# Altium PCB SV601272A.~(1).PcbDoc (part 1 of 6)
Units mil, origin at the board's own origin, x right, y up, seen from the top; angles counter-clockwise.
Board outline 8300 x 9520 mil, 8 copper layers (Top Layer, Signal Layer 1, Signal Layer 2, Signal Layer 3, Signal Layer 4, Signal Layer 5, Signal Layer 6, Bottom Layer), stack 59.2 mil thick; 551 components, 303 nets, 1611 pads, 1923 vias.
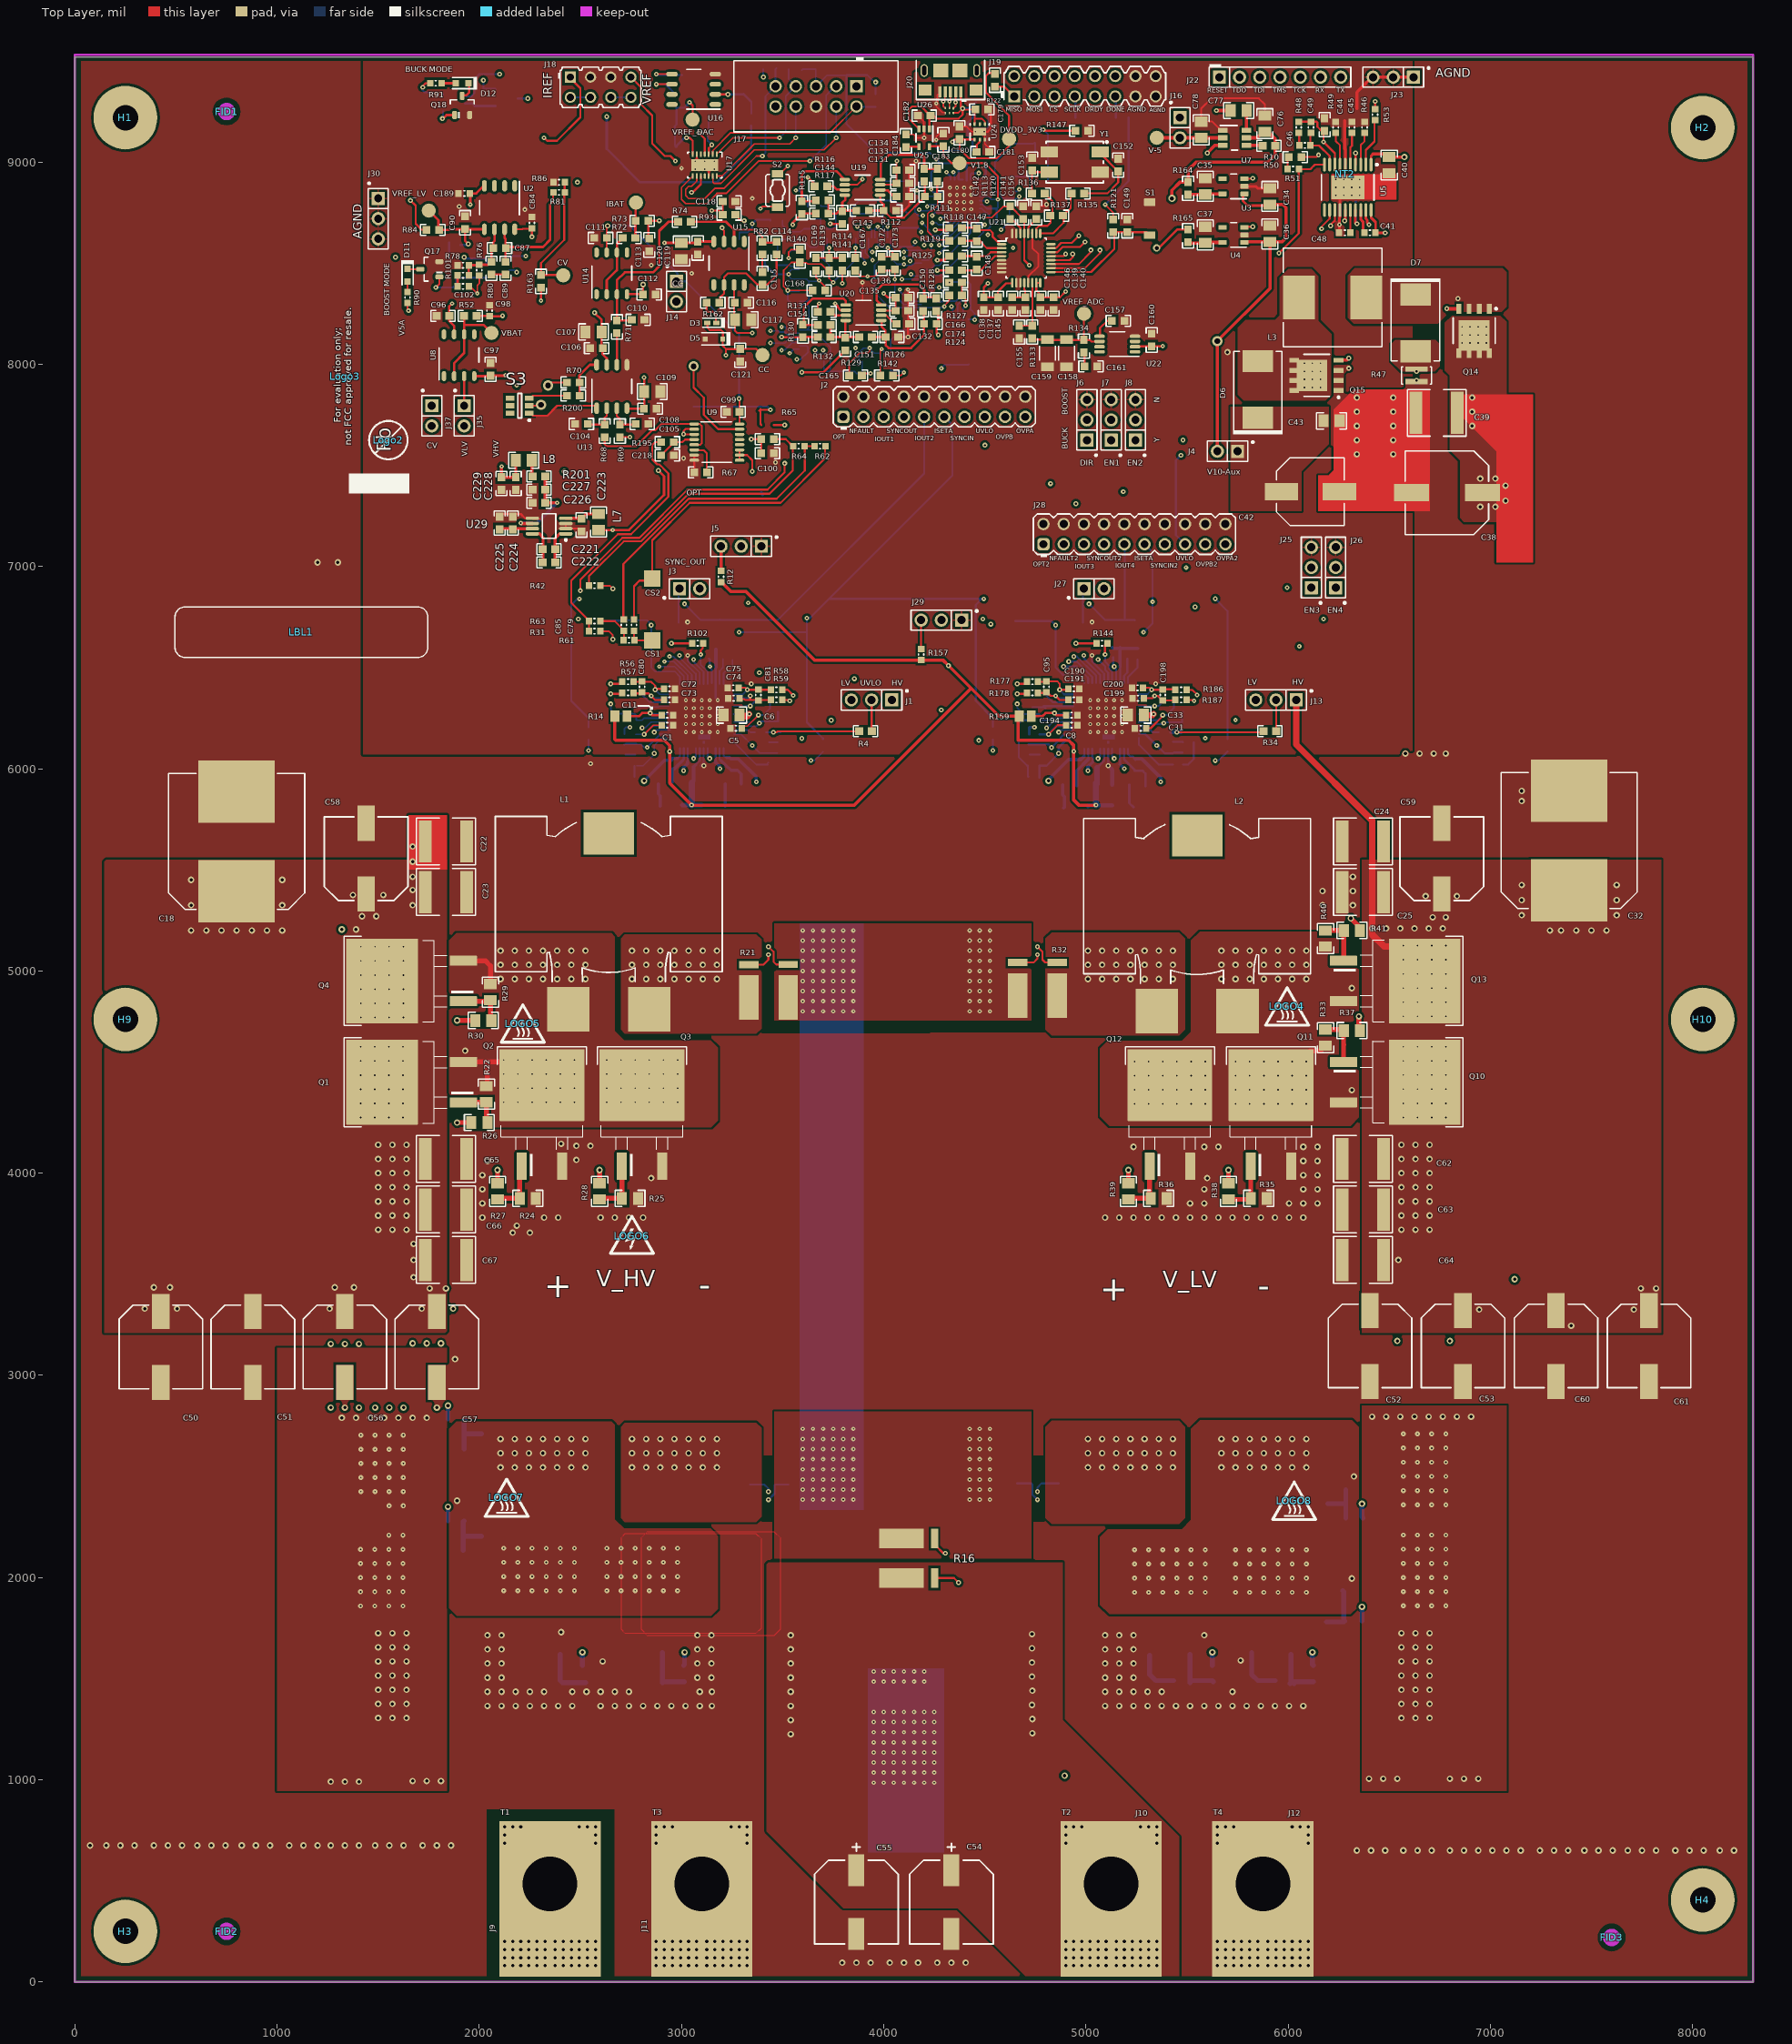
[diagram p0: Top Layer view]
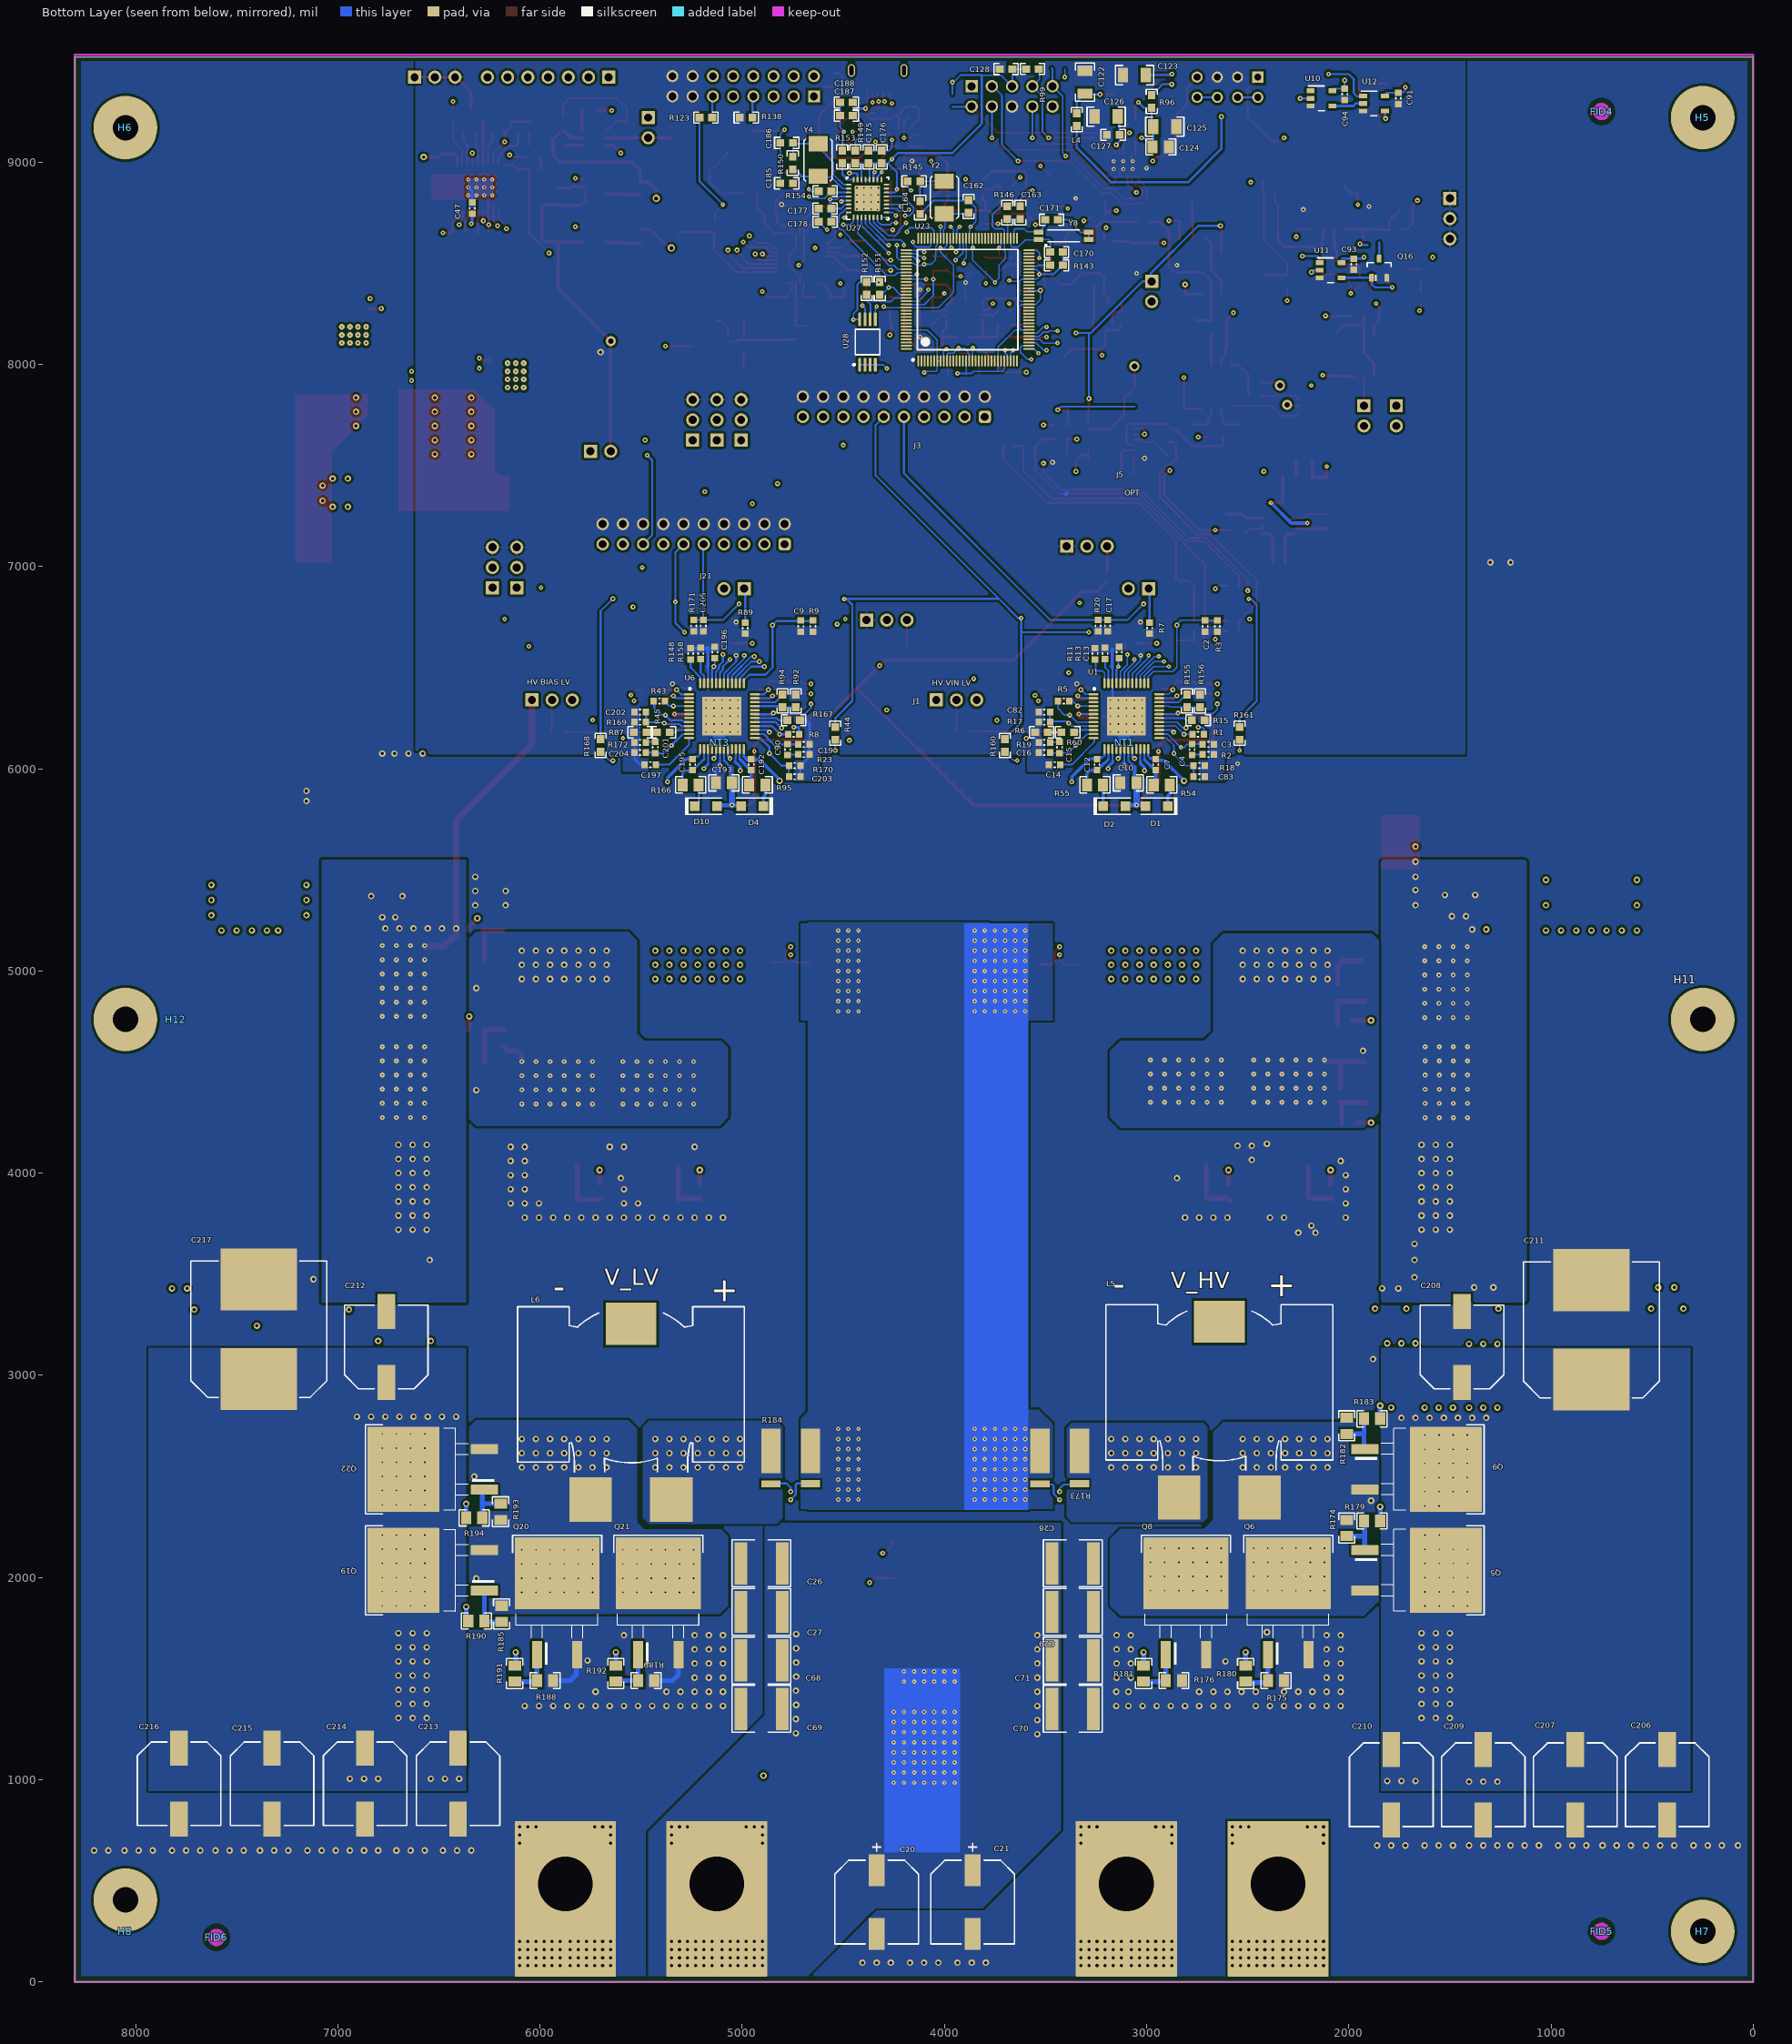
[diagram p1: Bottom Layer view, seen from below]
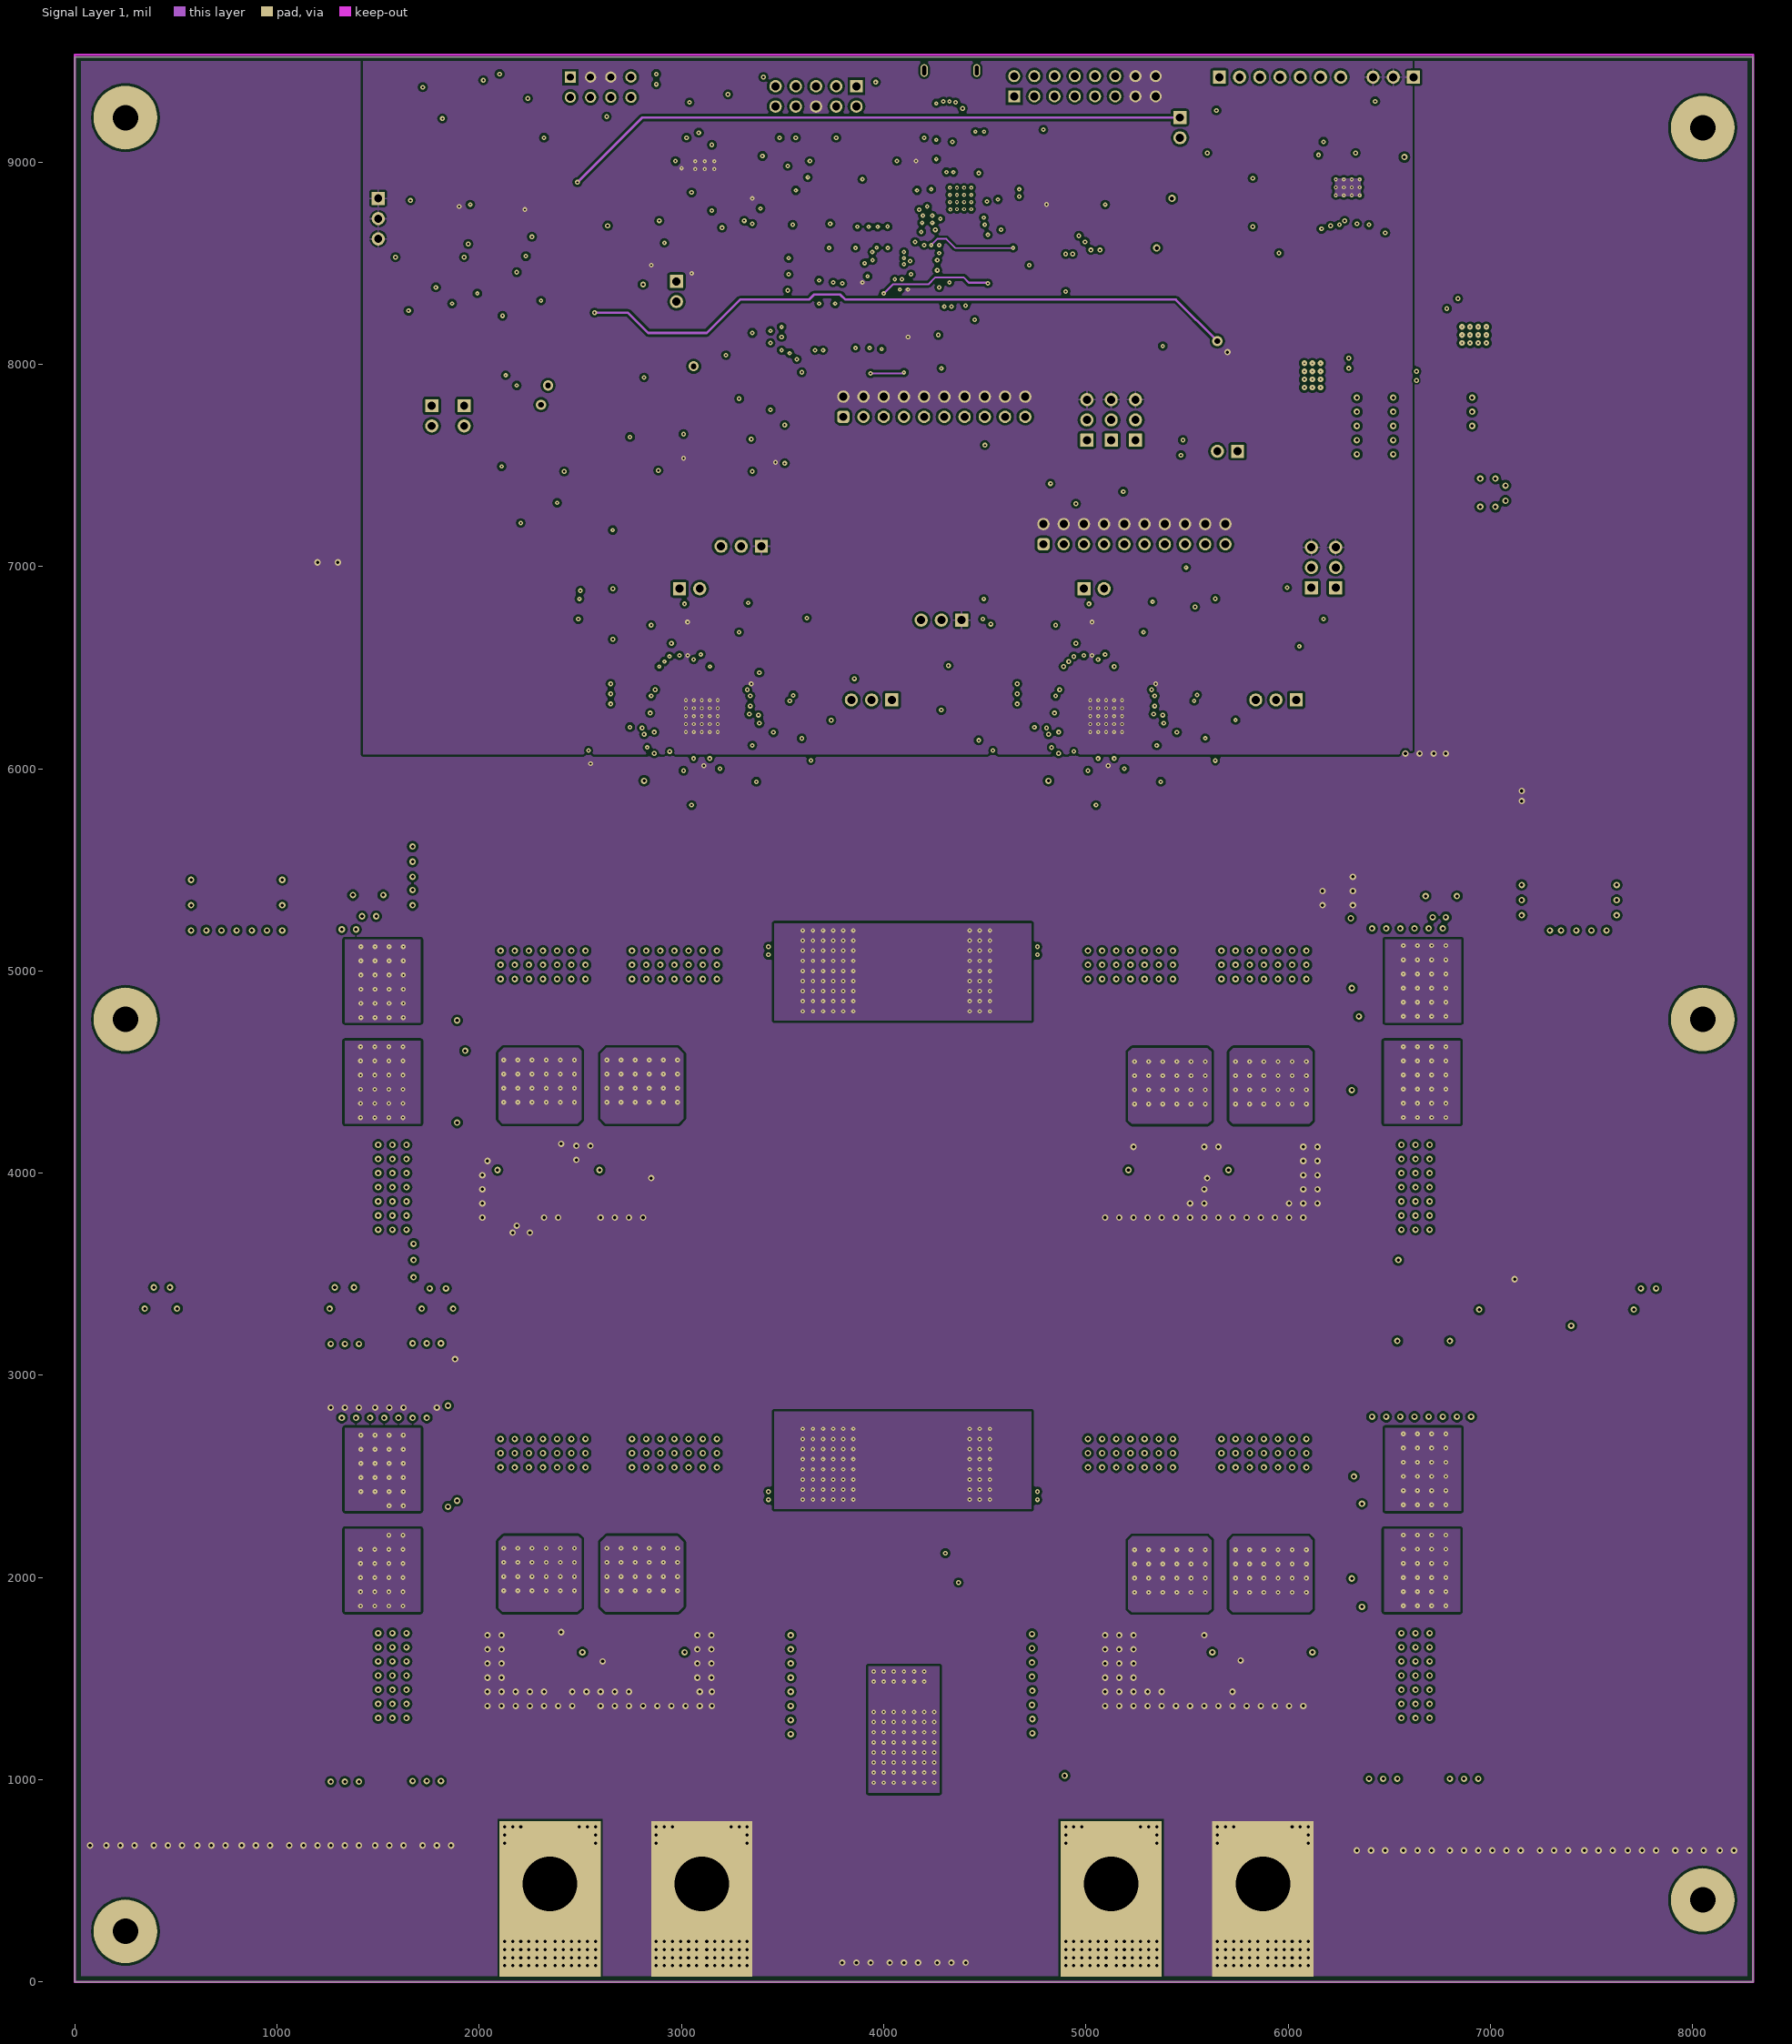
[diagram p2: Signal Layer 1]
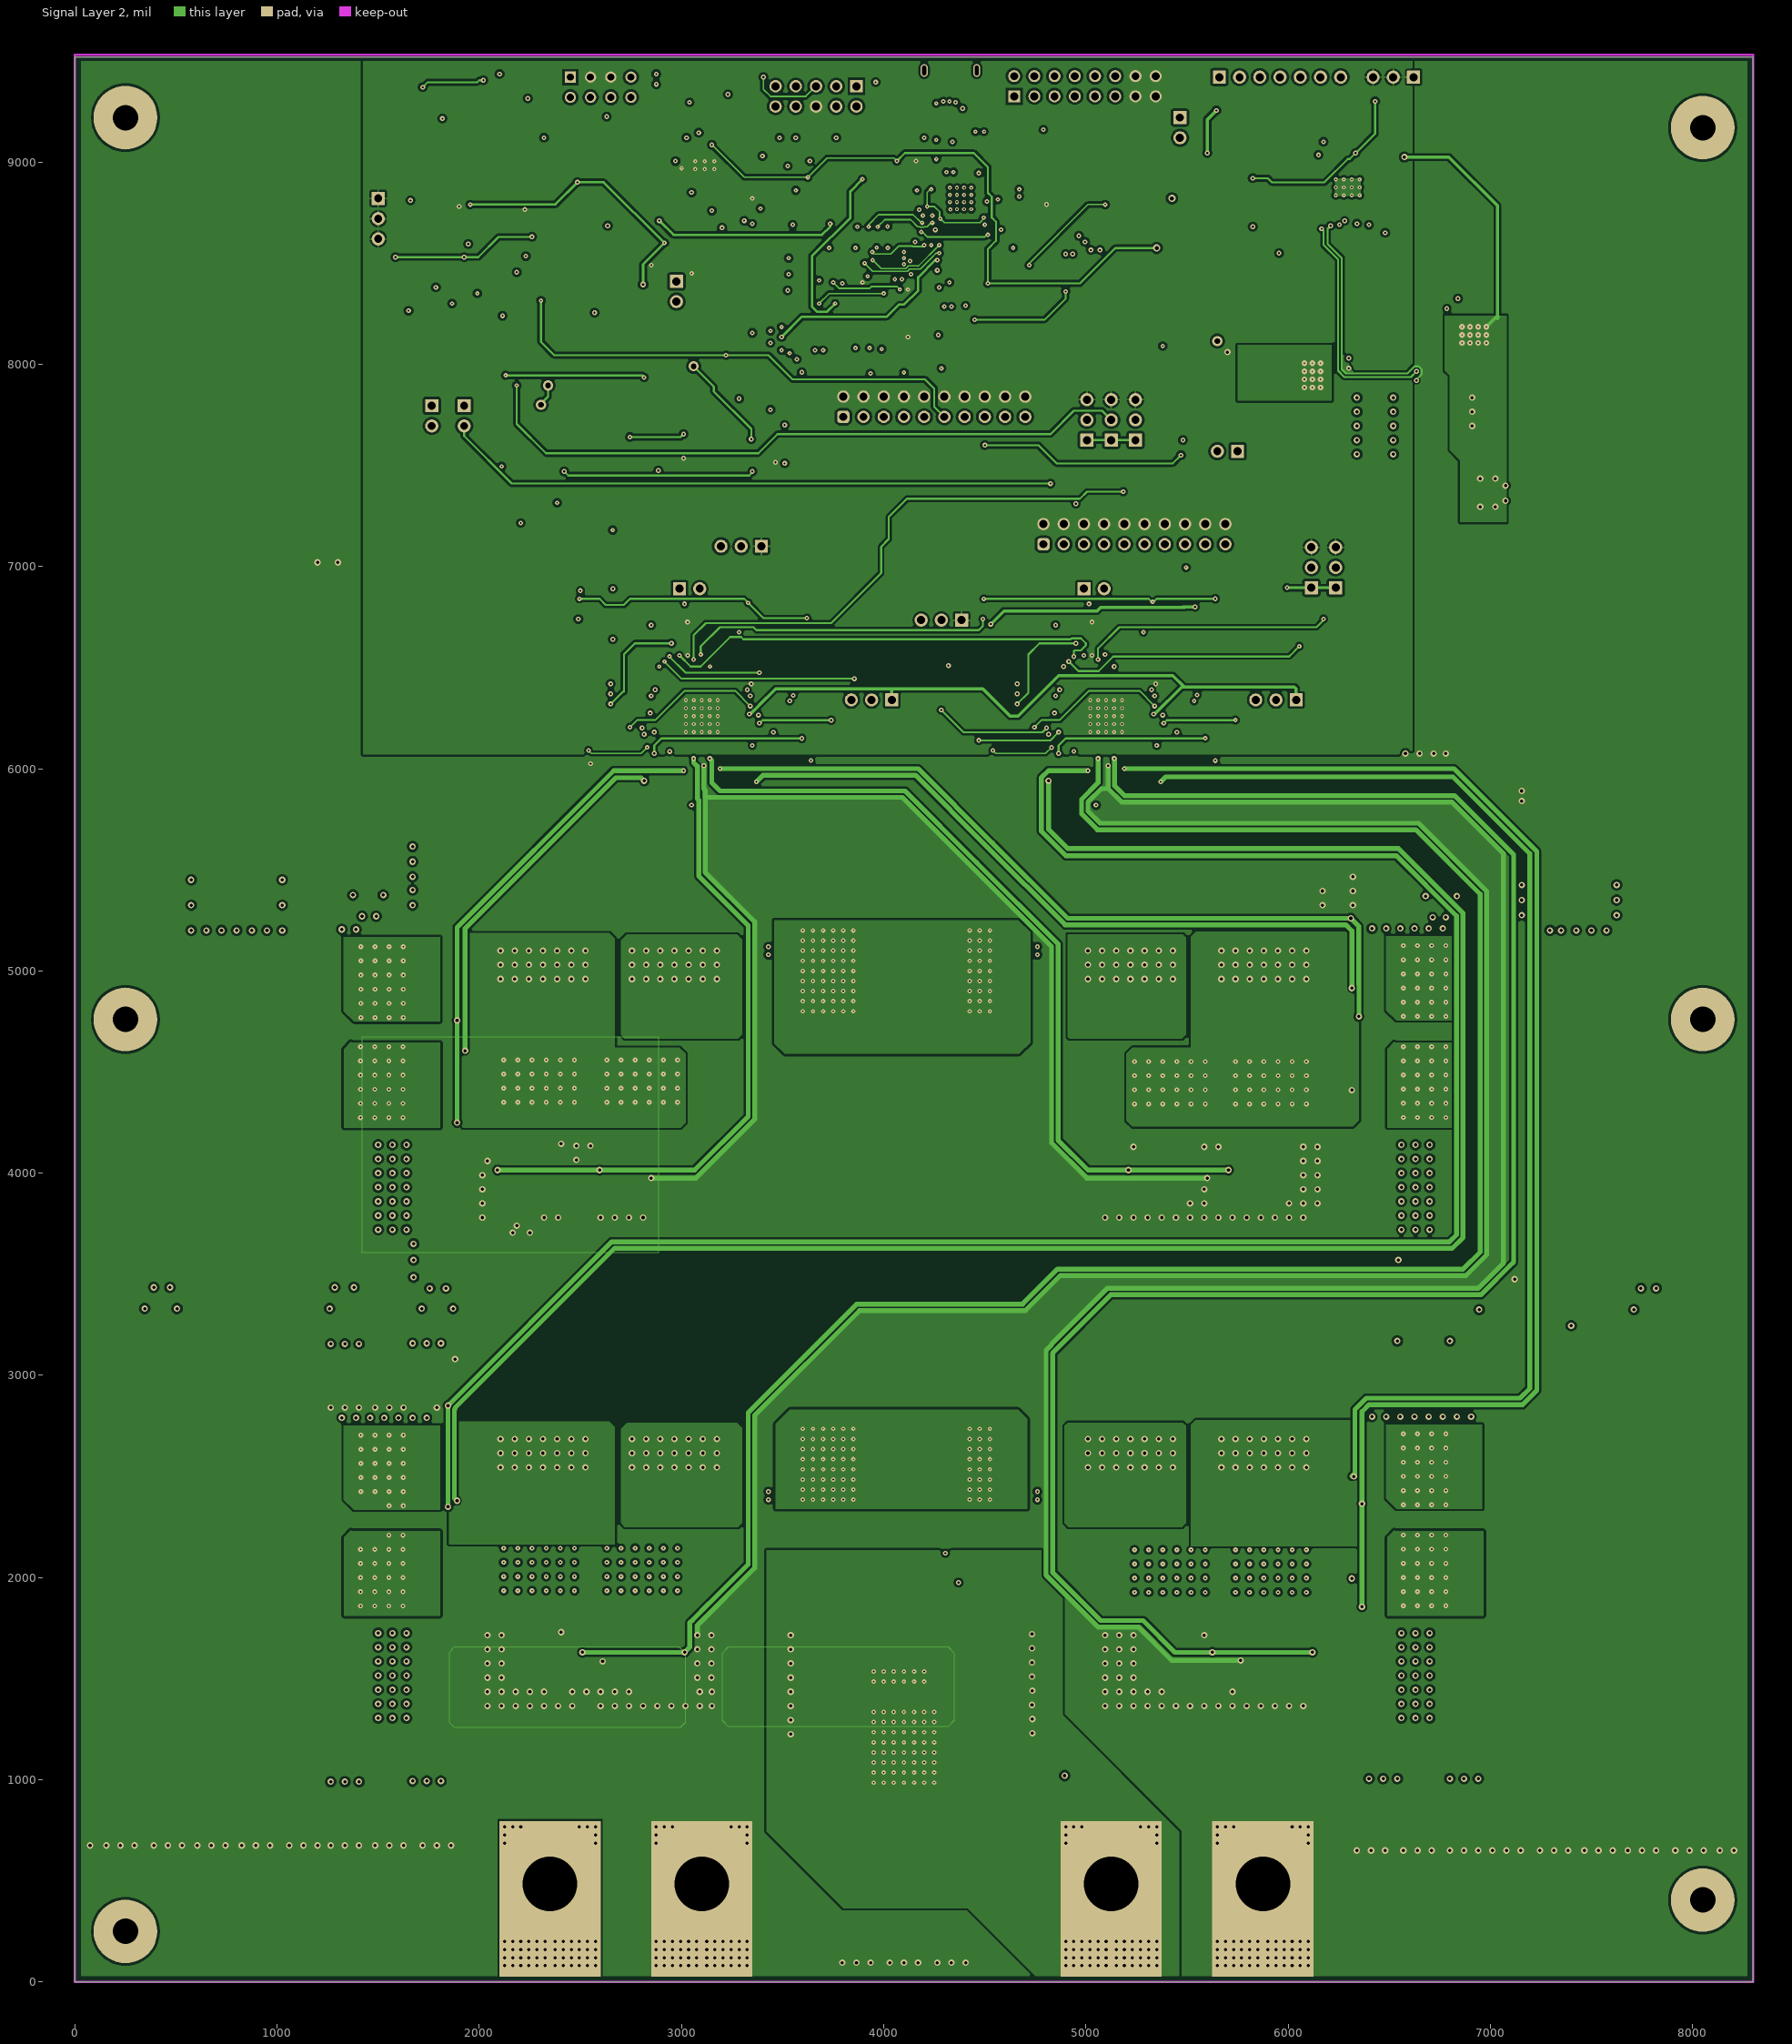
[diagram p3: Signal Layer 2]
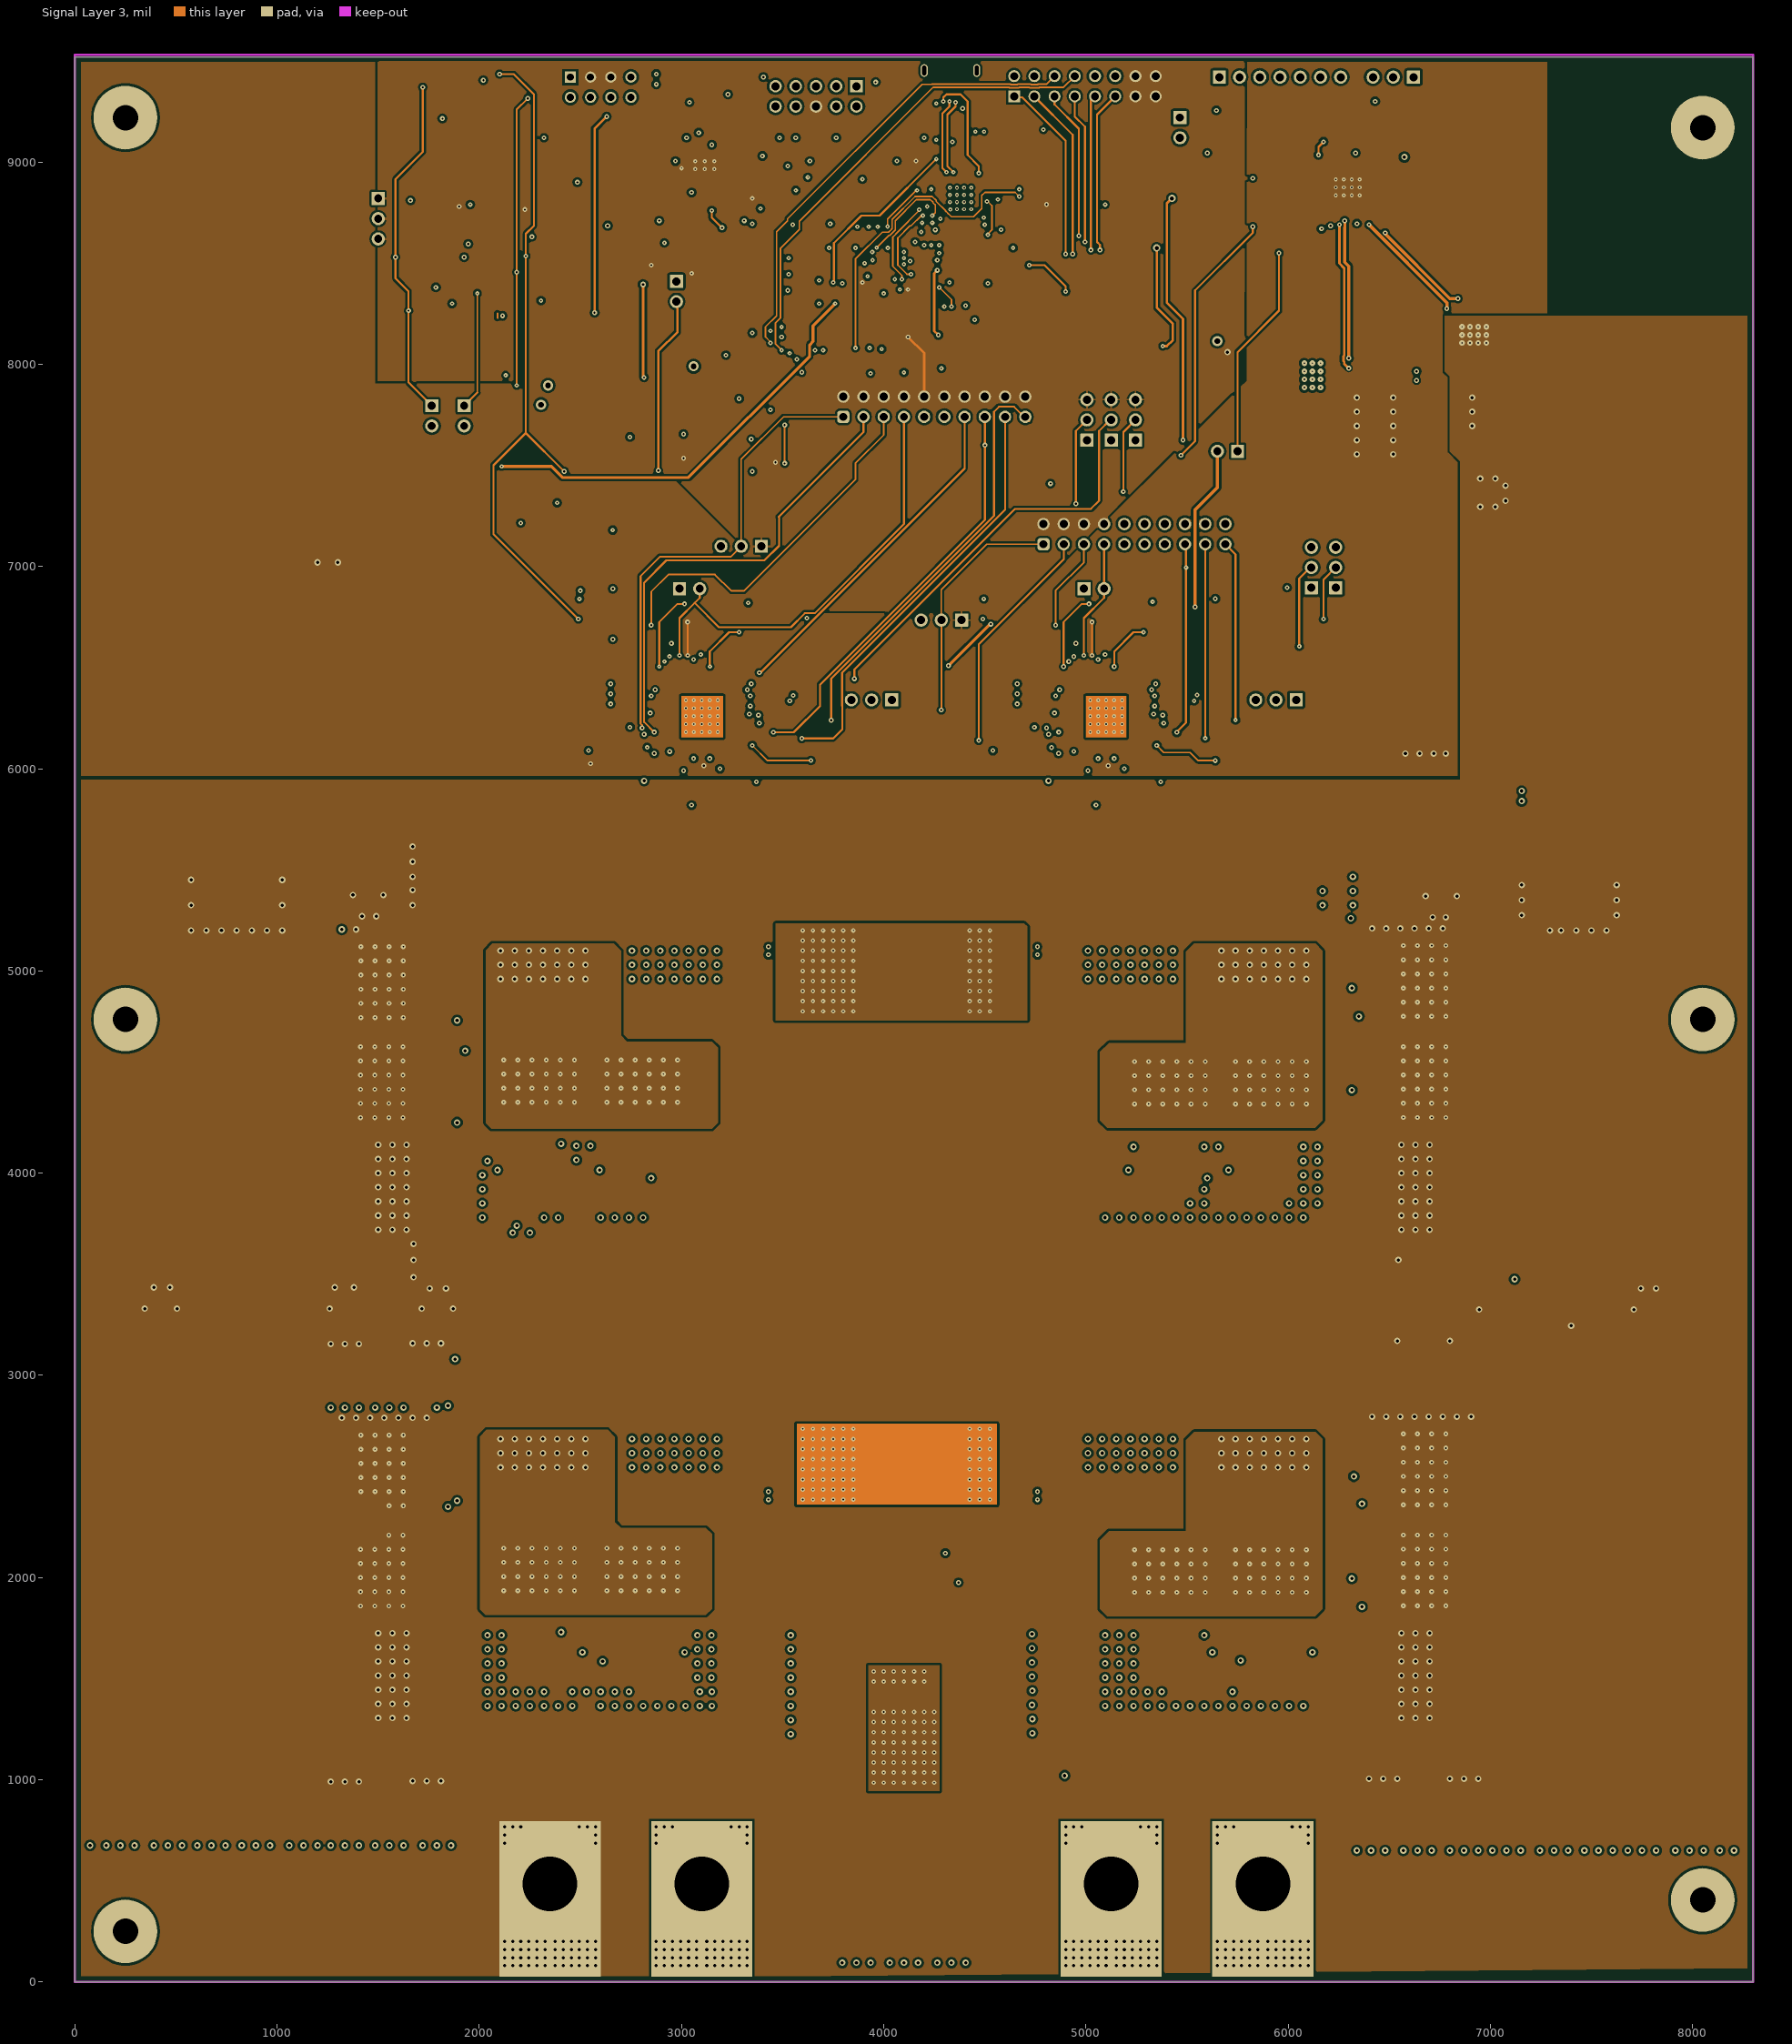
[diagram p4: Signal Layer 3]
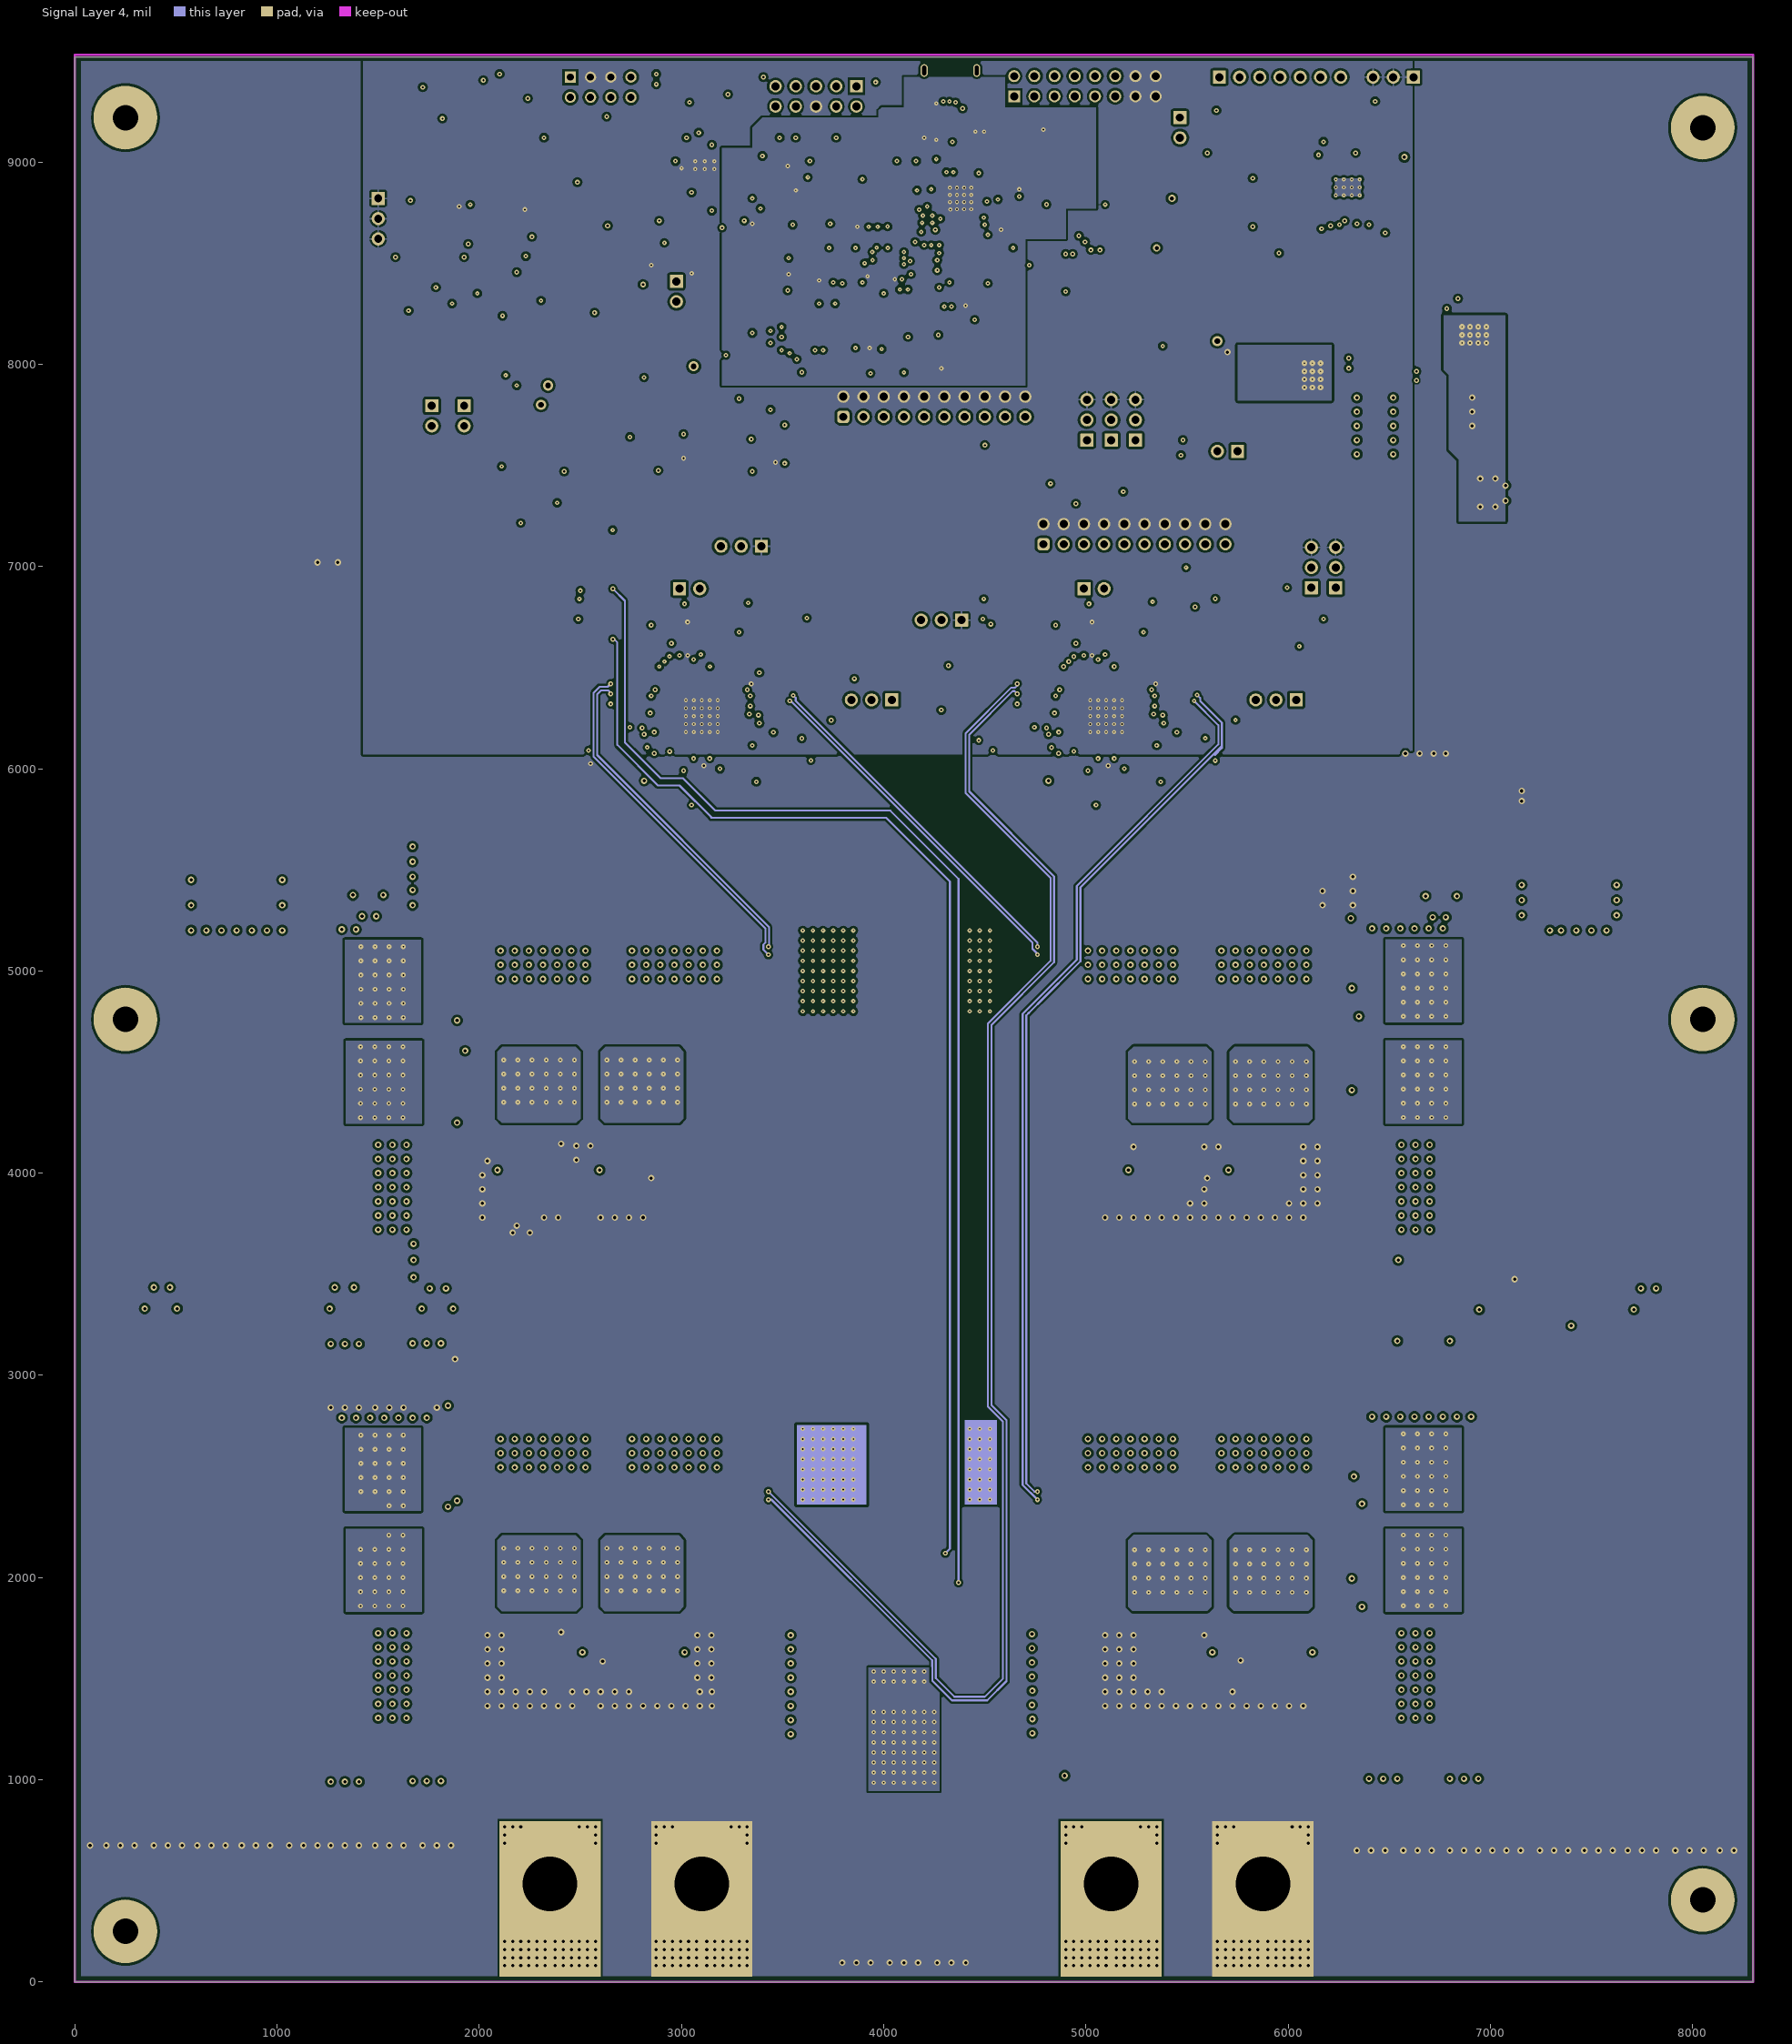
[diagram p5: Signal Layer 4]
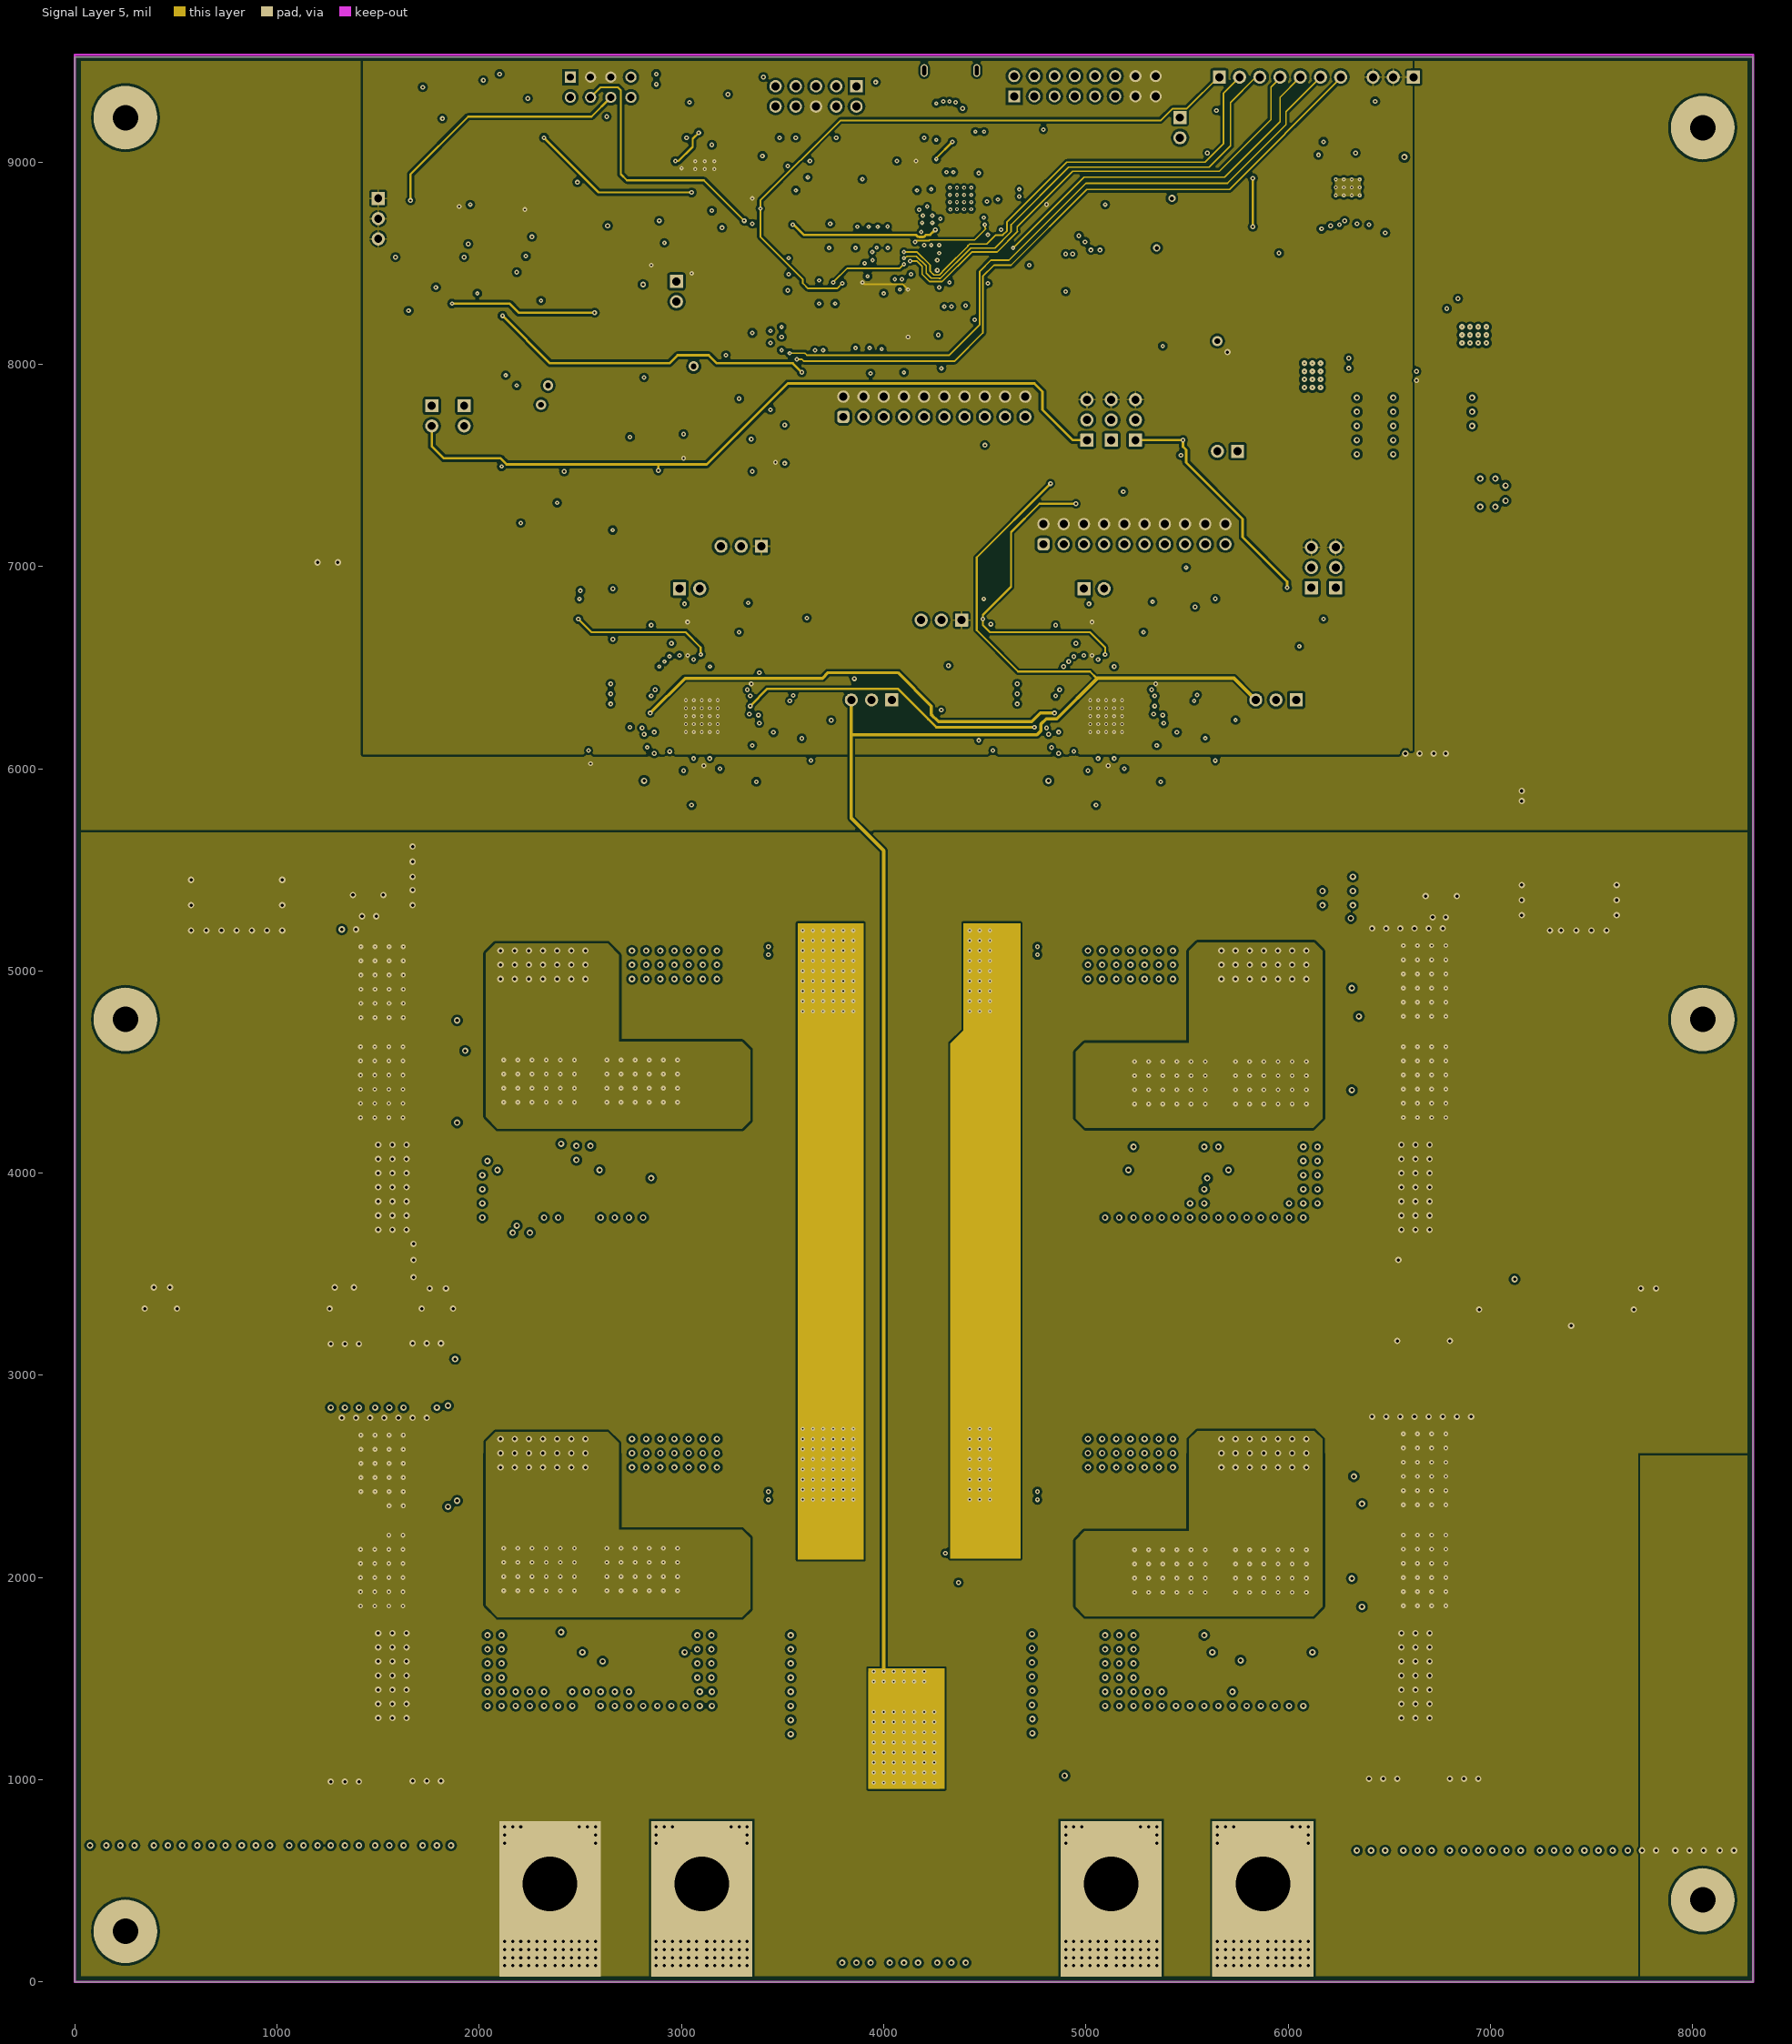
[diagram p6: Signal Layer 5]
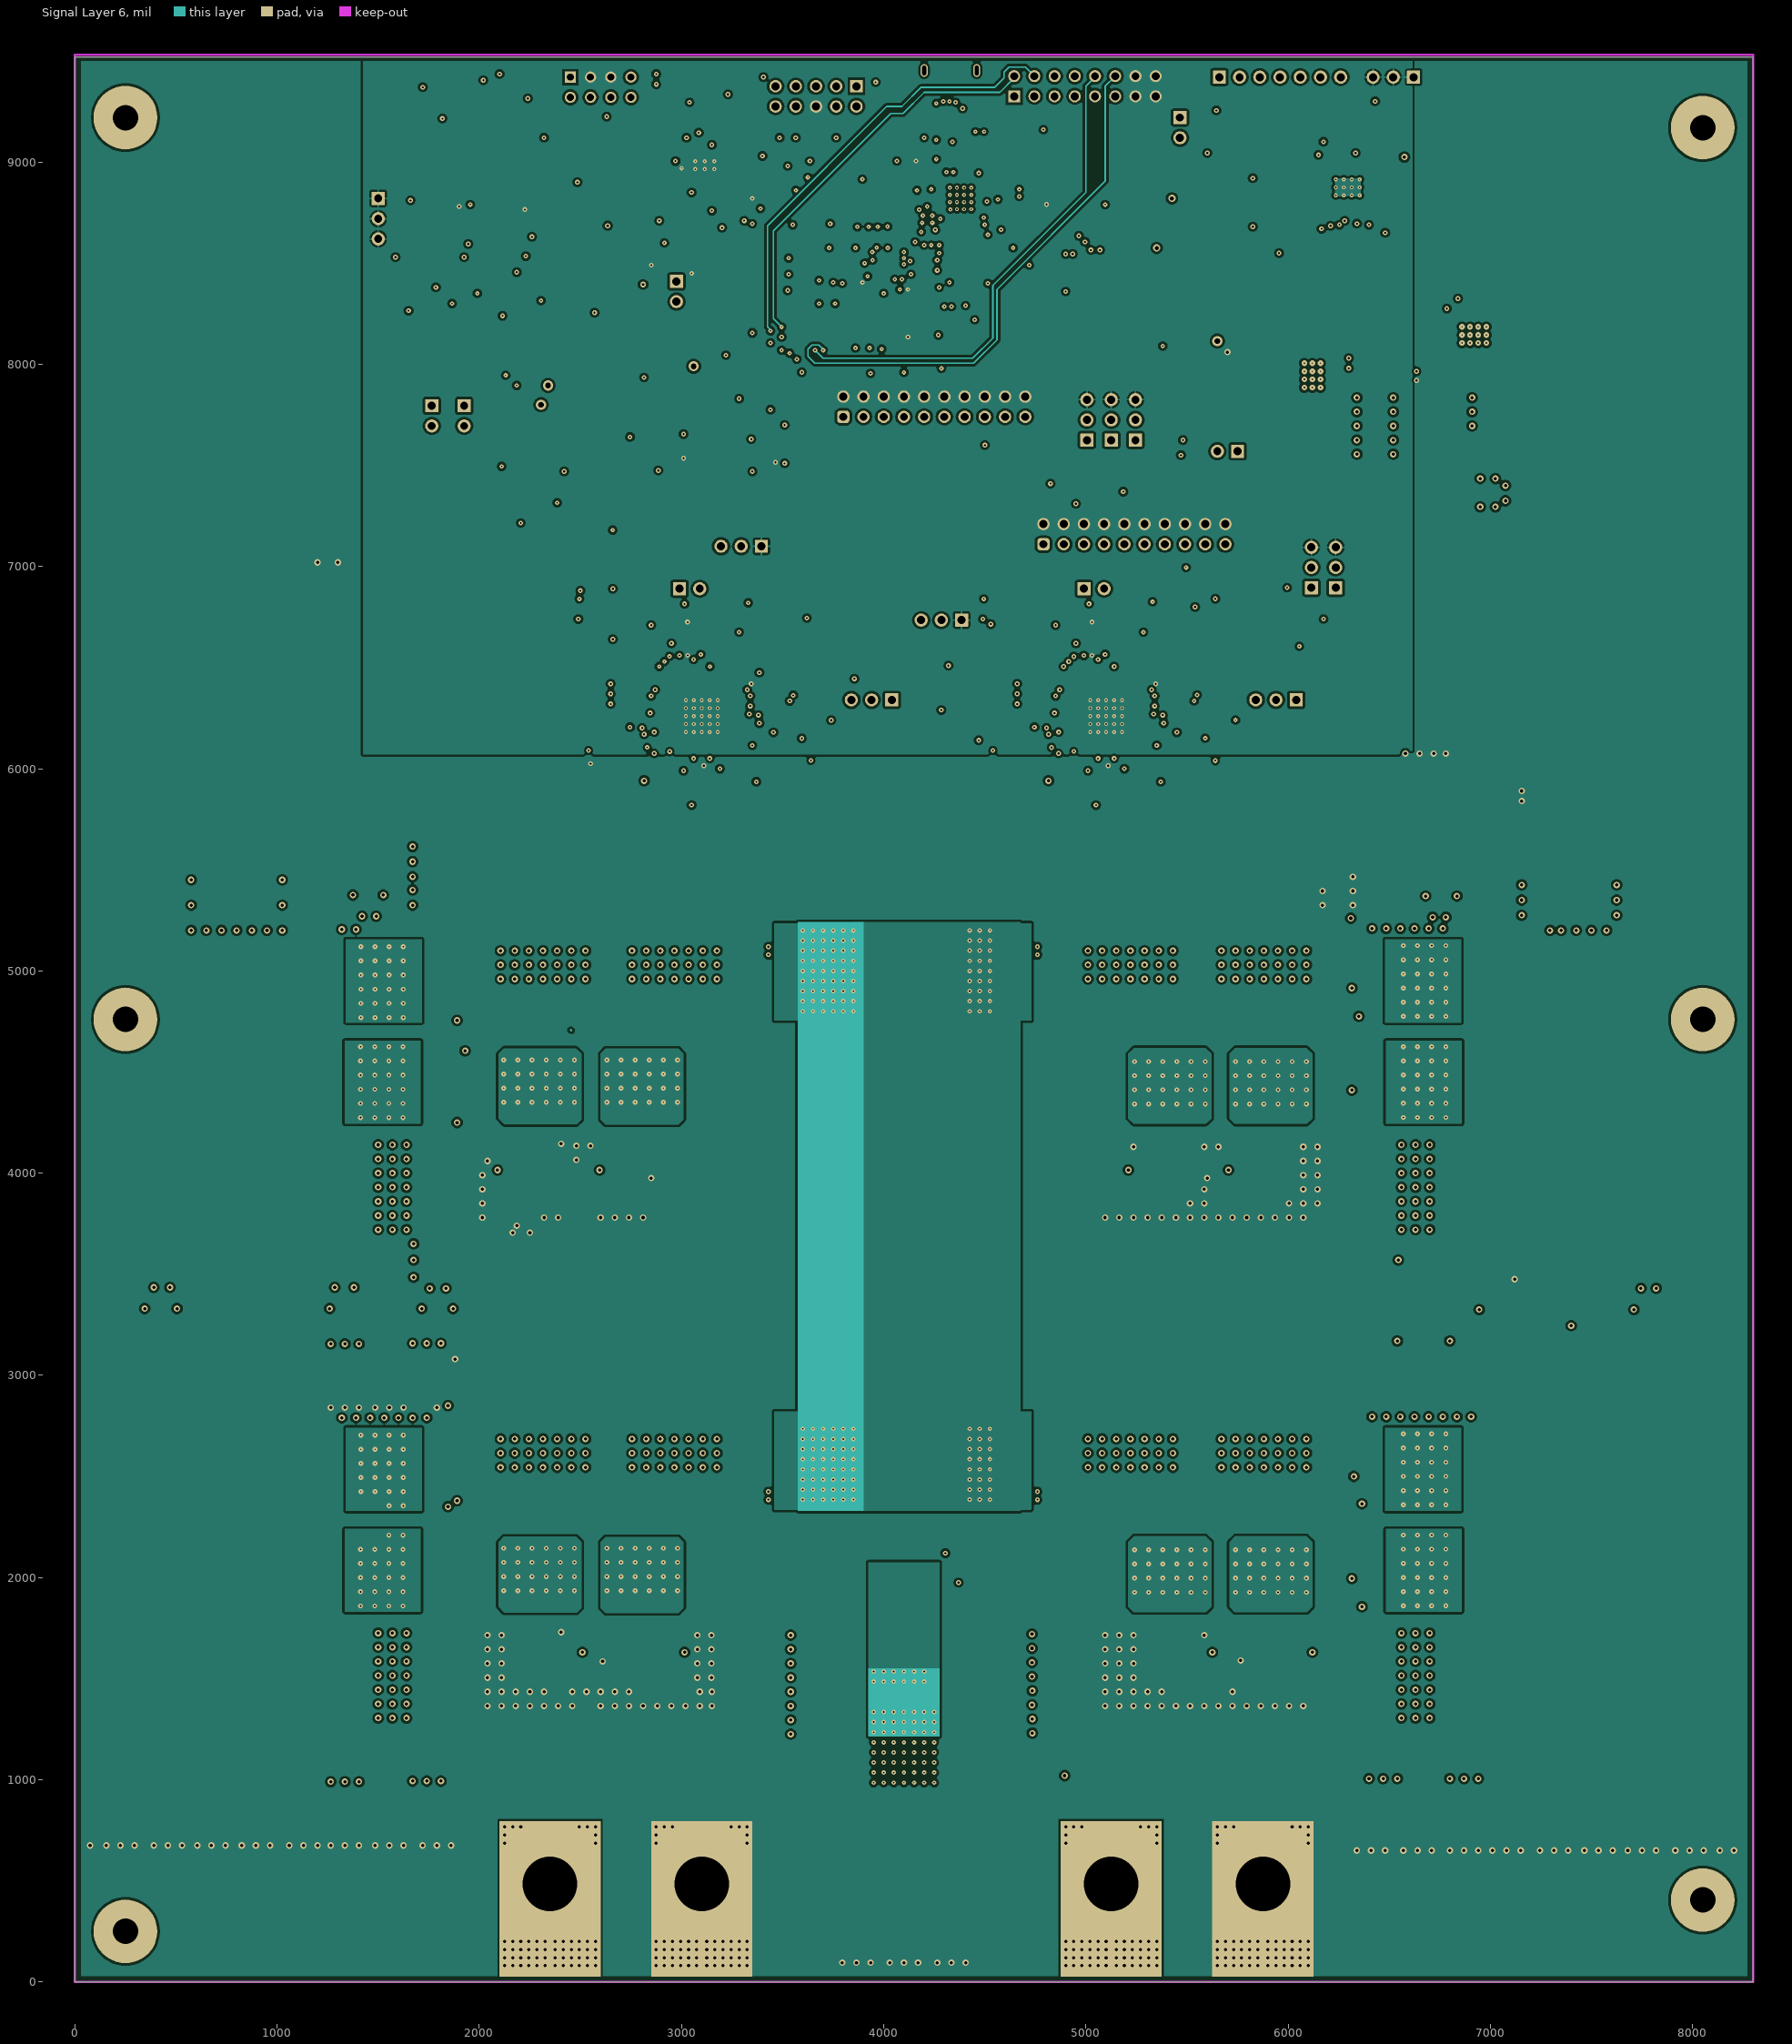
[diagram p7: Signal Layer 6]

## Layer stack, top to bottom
Top Solder: solder mask 0.4, Solder Resist, Dk 3.5
Top Layer: signal copper 3.2
Dielectric1: core 5, FR-4, Dk 4.8
Signal Layer 1: signal copper 2.8
Dielectric 2: prepreg 5, FR-4, Dk 4.2
Signal Layer 2: signal copper 2.8
Dielectric 3: core 5, FR-4, Dk 4.2
Signal Layer 3: signal copper 2.8
Dielectric4: prepreg 6, FR-4, Dk 4.2
Signal Layer 4: signal copper 2.8
Dielectric 5: core 5, FR-4, Dk 4.2
Signal Layer 5: signal copper 2.8
Dielectric 6: prepreg 5, FR-4, Dk 4.2
Signal Layer 6: signal copper 2.8
Dielectric 7: core 5, FR-4, Dk 4.2
Bottom Layer: signal copper 3.2
Bottom Solder: solder mask 0.4, Solder Resist, Dk 3.5

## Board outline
0,0 0,9520 8300,9520 8300,0

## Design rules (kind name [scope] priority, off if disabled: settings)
AcuteAngle [All] p1: minimum=3.30000000000000E+0001 checktracksonly=FALSE
AssemblyTestPointUsage [All] p1: valid=2
Clearance Clearance_USB [InComponent('J20') vs OnLayer('Keep-Out Layer')] p1: gap=30 ignorepadtopadclearanceinfootprint=FALSE
Clearance Clearance_Lugs2BoardEdge [HasFootprint('Panduit_CXS70-14-C') vs IsKeepOut] p2: gap=0 ignorepadtopadclearanceinfootprint=FALSE
Clearance Clearance_Keepouts [((IsTrack Or IsArc) And Not InPoly) And IsFree and IsKeepOut vs ((IsTrack Or IsArc) And Not InPoly) And IsFree and IsKeepOut] p3: gap=0 ignorepadtopadclearanceinfootprint=FALSE
Clearance Clearance_BoardEdge_MountingHoles [OnCopper and InComponentClass('Mounting Holes') vs IsKeepOut] p4: gap=40 ignorepadtopadclearanceinfootprint=FALSE except(0: Arc-Hole Track-Hole SMDPad-Hole THPad-Hole Via-Hole Fill-Hole Poly-Hole Region-Hole Text-Hole)
Clearance Clearance_BoardEdge_Poly [OnCopper and InPoly vs IsKeepOut] p5: gap=25 ignorepadtopadclearanceinfootprint=FALSE except(0: Arc-Hole Track-Hole SMDPad-Hole THPad-Hole Via-Hole Fill-Hole Poly-Hole Region-Hole Text-Hole)
Clearance Clearance_BoardEdge [OnCopper and Not InComponentClass('Logo') and not InComponentClass('FiducialMark') and not InRegion(1000,500,4000,800) and Not IsKeepout vs IsKeepOut] p6: gap=40 ignorepadtopadclearanceinfootprint=FALSE
Clearance Clearance_Poly [InPolygon] p7: gap=11.9 ignorepadtopadclearanceinfootprint=FALSE except(0: Arc-Hole Track-Hole SMDPad-Hole THPad-Hole Via-Hole Fill-Hole Poly-Hole Region-Hole Text-Hole)
Clearance [All] p8: gap=7.87 ignorepadtopadclearanceinfootprint=FALSE except(0: Arc-Hole Track-Hole SMDPad-Hole THPad-Hole Via-Hole Fill-Hole Poly-Hole Region-Hole Text-Hole)
ComponentClearance ComponentClearance_NetTie1 [HasFootprint('PHP0048D_L') vs HasFootprint('Net-Tie_10mil')] p1: gap=0 collisioncheckmode=3 verticalgap=0 showdistances=FALSE
ComponentClearance ComponentClearance_NetTie2 [HasFootprint('MXA20A_N') vs HasFootprint('Net-Tie_10mil')] p2: gap=0 collisioncheckmode=3 verticalgap=0 showdistances=FALSE
ComponentClearance ComponentClearance_Lugs2Banana [HasFootprint('Panduit_CXS70-14-C') vs HasFootprint('Johnson_108-0740-001')] p3: gap=0 collisioncheckmode=3 verticalgap=0 showdistances=FALSE
ComponentClearance ComponentClearance_MountingHoles_FiducialMarks [InComponentClass('Mounting Holes') vs InComponentClass('FiducialMark')] p4: gap=50 collisioncheckmode=3 verticalgap=10 showdistances=FALSE
ComponentClearance ComponentClearance_Shunt [InComponentClass('Header') vs InComponentClass('Shunt')] p5: gap=0 collisioncheckmode=3 verticalgap=0 showdistances=FALSE
ComponentClearance ComponentClearance_Logo [InComponentClass('Logo')] p6: gap=50 collisioncheckmode=3 verticalgap=10 showdistances=FALSE
ComponentClearance ComponentClearance_ScrewToNut [(HasFootprint('NY PMS 440 0025 PH')) vs HasFootprint('KEYSTONE_2205')] p7: gap=0 collisioncheckmode=3 verticalgap=0 showdistances=FALSE
ComponentClearance ComponentClearance_MountingHoles [InComponentClass('Mounting Holes')] p8: gap=100 collisioncheckmode=3 verticalgap=100000 showdistances=FALSE
ComponentClearance ComponentClearance_SmallPassives [HasFootprint('0201*') or HasFootprint('0402*') or HasFootprint('0508') or HasFootprint('0603*') or HasFootprint('0612') or HasFootprint('0805*') or HasFootprint('0815*') or HasFootprint('0830*') or HasFootprint('1206*') or HasFootprint('1210*') or HasFootprint('1808*') or HasFootprint('1812*') or HasFootprint('1825*') or HasFootprint('2010*') or HasFootprint('2220*') or HasFootprint('2225*') or HasFootprint('2512*') or HasFootprint('2728*') or HasFootprint('3518*') vs HasFootprint('0201*') or HasFootprint('0402*') or HasFootprint('0508') or HasFootprint('0603*') or HasFootprint('0612') or HasFootprint('0805*') or HasFootprint('0815*') or HasFootprint('0830*') or HasFootprint('1206*') or HasFootprint('1210*') or HasFootprint('1808*') or HasFootprint('1812*') or HasFootprint('1825*') or HasFootprint('2010*') or HasFootprint('2220*') or HasFootprint('2225*') or HasFootprint('2512*') or HasFootprint('2728*') or HasFootprint('3518*')] p9: gap=10 collisioncheckmode=3 verticalgap=10 showdistances=FALSE
ComponentClearance ComponentClearance_THtoSMT [IsThruComponent vs IsSMTComponent] p10: gap=20 collisioncheckmode=3 verticalgap=30 showdistances=FALSE
ComponentClearance ComponentClearance_THtoTH [IsThruComponent vs IsThruComponent] p11: gap=20 collisioncheckmode=3 verticalgap=30 showdistances=FALSE
ComponentClearance [All] p12: gap=30 collisioncheckmode=3 verticalgap=10 showdistances=FALSE
DiffPairsRouting [All] p1: maxlimit=100 minlimit=10 mostfreqgap=10 toplayer_minwidth=15 toplayer_maxwidth=15 toplayer_prefwidth=15 midlayer1_minwidth=15 midlayer1_maxwidth=15 midlayer1_prefwidth=15 midlayer2_minwidth=15 midlayer2_maxwidth=15 midlayer2_prefwidth=15 midlayer3_minwidth=15 midlayer3_maxwidth=15 midlayer3_prefwidth=15 midlayer4_minwidth=15 midlayer4_maxwidth=15 midlayer4_prefwidth=15 midlayer5_minwidth=15 midlayer5_maxwidth=15 midlayer5_prefwidth=15 midlayer6_minwidth=15 midlayer6_maxwidth=15 midlayer6_prefwidth=15 bottomlayer_minwidth=15 bottomlayer_maxwidth=15 bottomlayer_prefwidth=15 maxuncoupledlength=1000
FabricationTestPointUsage TestPointUsage [All] p1: valid=2 allowmultiple=FALSE
FabricationTestpoint Testpoint [All] p1: side=3 testpointundercomponent=TRUE minsize=40 maxsize=100 preferedsize=60 minholesize=0 maxholesize=40 preferedholesize=32 testpointgrid=1 allowsidetop=TRUE allowsidebottom=TRUE usegrid=TRUE gridtolerance=0.01
FanoutControl Fanout_LCC [IsLCC] p1: bgadir=Out bgaviamode=Centered fanoutstyle=Auto fanoutdirection=Alternating viagrid=1 // Fanout_LCC (Default Rule)
FanoutControl Fanout_BGA [IsBGA] p2: bgadir=Out bgaviamode=Centered fanoutstyle=Auto fanoutdirection=Alternating viagrid=1 // Fanout_BGA (Default Rule)
FanoutControl Fanout_Default [All] p4: bgadir=Out bgaviamode=Centered fanoutstyle=Auto fanoutdirection=Alternating viagrid=1 // Fanout_Default (Default Rule)
FanoutControl Fanout_Small [(CompPinCount < 5)] p5: bgadir=Out bgaviamode=Centered fanoutstyle=Auto fanoutdirection=OutThenIn viagrid=1 // Fanout_Small (Default Rule)
Height [All] p1: minheight=0 maxheight=1010 prefheight=500
HoleSize [All] p1: absolutevalues=TRUE maxlimit=500 minlimit=7.87 maxpercent=80.000 minpercent=20.000
HoleToHoleClearance I/OHoleClearance [HasFootprint('Johnson_108-0740-001') vs HasFootprint('Panduit_CXS70-14-C')] p1: gap=0 allowstackedmicrovias=TRUE
HoleToHoleClearance [All] p2: gap=10 allowstackedmicrovias=TRUE
MinimumAnnularRing MinimumAnnularRing_ThermalPadVias [IsVia and InAnyComponent] p1: minimumring=5.84
MinimumAnnularRing [All] p2: minimumring=7
MinimumSolderMaskSliver MinimumSolderMaskSliver_Logo [InComponentClass('Logo') vs InComponentClass('Logo')] p1: minsoldermaskwidth=0.7
MinimumSolderMaskSliver [All] p2: minsoldermaskwidth=1.9
PlaneConnect [All] p1: planeconnectstyle=Relief reliefexpansion=10 reliefentries=4 reliefconductorwidth=10 reliefairgap=10
PolygonConnect PolygonConnect_AGND [InNet('AGND') vs (HasFootprint('SAMTEC_HMTSW-130-07-G-D-240') OR HasFootprint('Samtec_HTSW-102-07-G-S') OR HasFootprint('Samtec_HTSW-103-07-G-S'))] p1: connectstyle=Relief reliefconductorwidth=10 reliefentries=4 polygonreliefangle="90 Angle" airgapwidth=10
PolygonConnect [All] p2: connectstyle=Direct reliefconductorwidth=10 reliefentries=4 polygonreliefangle="90 Angle" airgapwidth=10
RoutingVias ThermalPadVias [IsVia and InAnyComponent] p1: holewidth=7.87 width=19.68 viastyle="Through Hole" minholewidth=7.87 minwidth=19.68 maxholewidth=16 maxwidth=32
RoutingVias [All] p2: holewidth=16 width=32 viastyle="Through Hole" minholewidth=7.87 minwidth=20 maxholewidth=40 maxwidth=65
SilkToBoardRegionClearance [NOT ((IsComment OR IsDesignator) AND (Hide <> 'FAIL'))AND NOT InRegion (100,-500,8000,1500)] p1:
SilkToSilkClearance SilkToSilkClearance_Pb-FreeLogo [(HasFootprint('Pb-Free_Overlay_Medium') OR HasFootprint('Pb-Free_Overlay_Small')) vs (HasFootprint('Pb-Free_Overlay_Medium') OR HasFootprint('Pb-Free_Overlay_Small'))] p1: silktosilkclearance=0
SilkToSilkClearance [All] p2: silktosilkclearance=5
SilkToSolderMaskClearance "Silk to Solder Mask Opening" [All] p1: minsilkscreentomaskgap=1 clearancetoexposedcopper=FALSE
SolderMaskExpansion [All] p1: expansion=1.97
Width [All] p1: maxlimit=100 minlimit=6 preferedwidth=10 checkconnectedcopper=TRUE
13 further rules are at their usual default settings.

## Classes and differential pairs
component class "SV601272A-Current-Control REV3": C99 C100 C104 C105 C106 C107 C108 C109 C110 C111 C112 C113 C114 C115 C116 C117 C118 C119 C120 C121 C218 CC D3 D5 IBAT J14 J30 R65 R67 R68 R69 R70 R71 R72 R73 R74 R82 R93 R162 R195 R200 S3 U9 U13 U14 U15
component class SV601272A-Bias: C34 C35 C36 C37 C38 C39 C40 C41 C42 C43 C44 C45 C46 C47 C48 C49 C76 C77 C78 C221 C222 C223 C224 C225 C226 C227 C228 C229 D6 D7 J4 J16 J23 L3 L7 L8 NT2 Q14 Q15 R10 R46 R47 R48 R49 R50 R51 R53 R164 R165 R201 U3 U4 U5 U7 U29 V-5
component class SV601272A-Power: C18 C20 C21 C22 C23 C24 C25 C26 C27 C28 C29 C32 C50 C51 C52 C53 C54 C55 C56 C57 C58 C59 C60 C61 C62 C63 C64 C65 C66 C67 C68 C69 C70 C71 C79 C85 CS1 CS2 J9 J10 J11 J12 L1 L2 Q1 Q2 Q3 Q4 Q10 Q11 Q12 Q13 R16 R21 R22 R24 R25 R26 R27 R28 R29 R30 R31 R32 R33 R35 R36 R37 R38 R39 R40 R41 R42 R56 R57 R58 R59 R61 R62 R63 R64 T1 T2 T3 T4
component class SV601272A-Controller1: C1 C2 C3 C4 C5 C6 C7 C10 C11 C12 C13 C14 C15 C16 C17 C72 C73 C74 C75 C80 C81 C82 C83 D1 D2 J1 J2 J3 J5 J6 J7 J8 NT1 R1 R2 R3 R4 R5 R6 R7 R11 R12 R13 R14 R15 R17 R18 R19 R20 R54 R55 R60 R102 R155 R156 R160 R161 U1
component class "Mounting Holes": H1 H2 H3 H4 H9 H10
component class Label: LBL1
component class FiducialMark: FID1 FID2 FID3 FID4 FID5 FID6
component class SV601272A-HW: FID1 FID2 FID3 FID4 FID5 FID6 H1 H2 H3 H4 H5 H6 H7 H8 H9 H10 H11 H12 LBL1 Logo2 Logo3 LOGO4 LOGO5 LOGO6 LOGO7 LOGO8 ZZ1 ZZ2 ZZ3 ZZ4
component class AssemblyNote: ZZ1 ZZ2 ZZ3 ZZ4
component class Header: J1 J2 J3 J4 J5 J6 J7 J8 J13 J14 J16 J18 J19 J22 J23 J25 J26 J27 J28 J29 J30 J35 J37
component class SV601272A-Analog: C84 C87 C89 C90 C91 C93 C94 C96 C97 C98 C102 C189 CV D11 D12 J35 J37 Q16 Q17 Q18 R52 R76 R78 R80 R81 R84 R86 R90 R91 R101 R163 U2 U8 U10 U11 U12 VBAT VREF VREF_LV
component class SV601272A-DAC: C122 C123 C124 C125 C126 C127 C128 J17 J18 L4 R96 R99 U16 U17 VREF_DAC
component class SV601272A-ADC: C131 C132 C133 C134 C135 C136 C137 C138 C139 C140 C141 C142 C143 C144 C145 C146 C147 C148 C149 C150 C151 C152 C153 C154 C155 C156 C157 C158 C159 C160 C161 J19 R111 R112 R113 R114 R115 R116 R117 R118 R119 R120 R121 R122 R123 R124 R125 R126 R127 R128 R129 R130 R131 R132 R133 R134 R135 R136 R137 R138 S1 U19 U20 U21 U22 VREF_ADC Y1
component class SV601272A-TM4C_Main: C162 C163 C164 C165 C166 C167 C168 C169 C170 C171 C172 C173 C174 J22 R139 R140 R141 R142 R143 R145 R146 S2 U23 Y2 Y3
component class SV601272A-TM4C_Power: C175 C176 C177 C178 C179 C180 C181 C182 C183 C184 C185 C186 C187 C188 DVDD_3V3 J20 R147 R149 R150 R151 R152 R153 R154 U24 U25 U26 U27 U28 V1.8 Y4
component class ThermalPads: U24
component class "SV601272A-Power2 REV2": C206 C207 C208 C209 C210 C211 C212 C213 C214 C215 C216 C217 L5 L6 Q5 Q6 Q8 Q9 Q19 Q20 Q21 Q22 R173 R174 R175 R176 R177 R178 R179 R180 R181 R182 R183 R184 R185 R186 R187 R188 R189 R190 R191 R192 R193 R194
component class SV601272A-Controller2: C8 C9 C19 C30 C31 C33 C95 C190 C191 C192 C193 C194 C195 C196 C197 C198 C199 C200 C201 C202 C203 C204 C205 D4 D10 J13 J25 J26 J27 J28 J29 NT3 R8 R9 R23 R34 R43 R44 R45 R87 R89 R92 R94 R95 R144 R148 R157 R158 R159 R166 R167 R168 R169 R170 R171 R172 U6

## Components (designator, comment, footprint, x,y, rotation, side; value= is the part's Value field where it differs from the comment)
C1 "C1608C0G2A102J080AA" 0603L 2930,6215 r0 top value=1000pF
C2 "06031C103KAT2A" 0603L 2710,6705 r90 bottom value=0.01uF
C3 "C1608C0G2A102J080AA" 0603L 2695,6120 r0 bottom value=1000pF
C4 "GRM188R71E153KA01D" 0603L 2775,6095 r90 bottom value=0.015uF
C5 "C1608C0G2A102J080AA" 0603L 3270,6200 r180 top value=1000pF
C6 "C2012X7S2A105K125AB" 0805_HV 3247,6265 r180 top value=1uF
C7 "C1608X7R1H224K080AB" 0603L 2955,6020 r270 bottom value=0.22uF
C8 "C1608C0G2A102J080AA" 0603L 4930,6215 r0 top value=1000pF
C9 "06031C103KAT2A" 0603L 4710,6705 r90 bottom value=0.01uF
C10 "C2012X7R1C225K125AB" 0805_HV 3090,5930 r0 bottom value=2.2uF
C11 "GRM188R71E105KA12D" 0603L 2930,6265 r0 top value=1uF
C12 "C1608X7R1H224K080AB" 0603L 3245,6020 r90 bottom value=0.22uF
C13 "C0603C101J5GACTU" 0603L 3135,6575 r90 bottom value=100pF
C14 "06031C103KAT2A" 0603L 3455,6020 r0 bottom value=0.01uF
C15 "GRM188R71E153KA01D" 0603L 3430,6105 r90 bottom value=0.015uF
C16 "C1608C0G2A102J080AA" 0603L 3505,6080 r0 bottom value=1000pF
C17 "06031C103KAT2A" 0603L 3192.48,6707.52 r270 bottom value=0.01uF
C18 "EMVH101GDA101MLH0S" CAPSMT_62_LH0 800,5640 r90 top value=100uF
C19 "C1608C0G2A102J080AA" 0603L 4695,6120 r0 bottom value=1000pF
C20 "PCR1H181MCL1GS" CR_1000x1270 4335,395 r270 bottom value=180uF
C21 "PCR1H181MCL1GS" CR_1000x1270 3860,395 r270 bottom value=180uF
C22 "C5750X7R2A475M230KA" 2220_280 1835,5640 r0 top value=4.7uF
C23 "C5750X7R2A475M230KA" 2220_280 1835,5390 r0 top value=4.7uF
C24 "C5750X7R2A475M230KA" 2220_280 6370,5640 r180 top value=4.7uF
C25 "C5750X7R2A475M230KA" 2220_280 6370,5390 r180 top value=4.7uF
C26 "C5750X7R2A475M230KA" 2220_280 4905,2070 r0 bottom value=4.7uF
C27 "C5750X7R2A475M230KA" 2220_280 4905,1830 r0 bottom value=4.7uF
C28 "C5750X7R2A475M230KA" 2220_280 3365,2070 r180 bottom value=4.7uF
C29 "C5750X7R2A475M230KA" 2220_280 3365,1830 r180 bottom value=4.7uF
C30 "GRM188R71E153KA01D" 0603L 4775,6095 r90 bottom value=0.015uF
C31 "C1608C0G2A102J080AA" 0603L 5270,6200 r180 top value=1000pF
C32 "EMVH101GDA101MLH0S" CAPSMT_62_LH0 7390,5645 r90 top value=100uF
C33 "C2012X7S2A105K125AB" 0805_HV 5247,6265 r180 top value=1uF
C34 "C2012X7S2A105K125AB" 0805_HV 5910,8830 r90 top value=1uF
C35 "C2012X7S2A105K125AB" 0805_HV 5590,8880 r90 top value=1uF
C36 "C2012X7S2A105K125AB" 0805_HV 5910,8645 r90 top value=1uF
C37 "C2012X7S2A105K125AB" 0805_HV 5590,8640 r90 top value=1uF
C38 "EMVH101ADA220MJA0G" CAPSMT_62_JA0 6785,7365 r180 top value=22uF
C39 "C5750X7S2A106M230KB" 2220_250 6735,7760 r180 top value=10uF
C40 "C2012X7R2A104K125AA" 0805_HV 6500,8985 r270 top value=0.1uF
C41 "GRM188R72A104KA35D" 0603L 6405,8650 r180 top value=0.1uF
C42 "APXA160ARA181MHC0G" CAPSMT_62_HC0 6110,7370 r0 top value=180uF
C43 "C2012X7R1C225K125AB" 0805_HV 6215,7720 r0 top value=2.2uF
C44 "GRM188R72A104KA35D" 0603L 6235.31,9172.2 r90 top value=0.1uF
C45 "C1608C0G2A331J080AA" 0603L 6315.31,9172.2 r90 top value=330pF
C46 "GRM188R71H563KA93D" 0603L 6082.52,9082.2 r180 top value=0.056uF
C47 "GRM188R71E105KA12D" 0603L 6335,8772 r90 bottom value=1uF
C48 "GRM188R71E105KA12D" 0603L 6280,8650 r180 top value=1uF
C49 "GRM1885C2A152JA01D" 0603L 6112.52,9172.2 r90 top value=1500pF
C50 "HHXA800ARA390MJA0G" HXA_JA0 425,3140 r270 top value=39uF
C51 "HHXA800ARA390MJA0G" HXA_JA0 880,3140 r270 top value=39uF
C52 "HHXA800ARA390MJA0G" HXA_JA0 6405,3145 r270 top value=39uF
C53 "HHXA800ARA390MJA0G" HXA_JA0 6865,3145 r270 top value=39uF
C54 "PCR1H181MCL1GS" CR_1000x1270 4335,395 r270 top value=180uF
C55 "PCR1H181MCL1GS" CR_1000x1270 3865,395 r270 top value=180uF
C56 "HHXA800ARA390MJA0G" HXA_JA0 1335,3140 r270 top value=39uF
C57 "HHXA800ARA390MJA0G" HXA_JA0 1790,3140 r270 top value=39uF
C58 "HHXA800ARA390MJA0G" HXA_JA0 1440,5555 r90 top value=39uF
C59 "HHXA800ARA390MJA0G" HXA_JA0 6760,5555 r90 top value=39uF
C60 "HHXA800ARA390MJA0G" HXA_JA0 7325,3145 r270 top value=39uF
C61 "HHXA800ARA390MJA0G" HXA_JA0 7785,3145 r270 top value=39uF
C62 "C5750X7R2A475M230KA" 2220_280 6370,4070 r180 top value=4.7uF
C63 "C5750X7R2A475M230KA" 2220_280 6370,3820 r180 top value=4.7uF
C64 "C5750X7R2A475M230KA" 2220_280 6370,3570 r180 top value=4.7uF
C65 "C5750X7R2A475M230KA" 2220_280 1835,4070 r0 top value=4.7uF
C66 "C5750X7R2A475M230KA" 2220_280 1835,3820 r0 top value=4.7uF
C67 "C5750X7R2A475M230KA" 2220_280 1835,3570 r0 top value=4.7uF
C68 "C5750X7R2A475M230KA" 2220_280 4905,1590 r0 bottom value=4.7uF
C69 "C5750X7R2A475M230KA" 2220_280 4905,1350 r0 bottom value=4.7uF
C70 "C5750X7R2A475M230KA" 2220_280 3365,1350 r180 bottom value=4.7uF
C71 "C5750X7R2A475M230KA" 2220_280 3365,1590 r180 bottom value=4.7uF
C72 "C0603C101J5GACTU" 0603L 2940,6395 r0 top value=100pF
C73 "C0603C101J5GACTU" 0603L 2940,6340 r0 top value=100pF
C74 "C0603C101J5GACTU" 0603L 3258.46,6348.58 r180 top value=100pF
C75 "C0603C101J5GACTU" 0603L 3255,6400 r180 top value=100pF
C76 "Capacitor" 0805_HV 5885,9190 r90 top value=1uF
C77 "Capacitor" 0805_HV 5755,9255 r180 top value=1uF
C78 "Capacitor" 0805_HV 5570,9160 r90 top value=1uF
C79 "Capacitor" 0603L 2765,6710 r270 top value=0.01uF
C80 "GRM188R71C474KA88D" 0603L 2805,6405 r270 top value=0.47uF
C81 "GRM188R71C474KA88D" 0603L 3380,6365 r90 top value=0.47uF
C82 "C0603C101J5GACTU" 0603L 3505,6280 r0 bottom value=100pF
C83 "C0603C101J5GACTU" 0603L 2740,5960 r180 bottom value=100pF
C84 "GRM188R72A104KA35D" 0603L 2260,8700 r90 top value=0.1uF
C85 "Capacitor" 0603L 2715,6710 r270 top value=0.01uF
C87 "C0603C100J5GACTU" 0603 2100,8575 r0 top value=10pF
C89 "C1608X5R1H104K080AA" 0603 2130,8475 r90 top value=0.1uF
C90 "EMK107BBJ106MA-T" 0603 1930,8700 r90 top value=10uF
C91 "GRM188R72A104KA35D" 0603L 1755,9315 r90 bottom value=0.1uF
C93 "GRM188R72A104KA35D" 0603L 1975,8495 r270 bottom value=0.1uF
C94 "GRM188R72A104KA35D" 0603L 2020,9335 r90 bottom value=0.1uF
C95 "GRM188R71C474KA88D" 0603L 4805,6405 r270 top value=0.47uF
C96 "Capacitor" 0603 1820,8240 r180 top value=0.1uF
C97 "Capacitor" 0603 2055,7975 r90 top value=0.1uF
C98 "Capacitor" 0603L 2050,8265 r90 top value=100pF
C99 "Capacitor" 0603 3255,7765 r0 top value=0.1uF
C100 "Capacitor" 0603 3425,7560 r0 top value=0.015uF
C102 "C0603C101J5GACTU" 0603L 1920,8385 r180 top value=100pF
C104 "Capacitor" 0603 2505,7705 r180 top value=0.015uF
C105 "Capacitor" 0603 2805,7705 r0 top value=0.015uF
C106 "Capacitor" 0603 2580,8080 r180 top value=0.1uF
C107 "Capacitor" 0805_HV 2565,8160 r180 top value=10uF
C108 "Capacitor" 0603 2845,7780 r0 top value=0.1uF
C109 "Capacitor" 0805_HV 2855,7865 r0 top value=10uF
C110 "GCM188R71H103KA37D" 0603 2785,8220 r0 top value=0.01uF
C111 "Capacitor" 0603 2600,8625 r180 top value=0.1uF
C112 "Capacitor" 0603 2840,8345 r0 top value=0.1uF
C113 "Capacitor" 0603 2840,8590 r90 top value=10pF
C114 "Capacitor" 0603 3470,8575 r270 top value=10pF
C115 "Capacitor" 0603 3400,8425 r90 top value=0.1uF
C116 "Capacitor" 0603 3295,8305 r0 top value=0.1uF
C117 "Capacitor" 0805_HV 3305,8220 r0 top value=10uF
C118 "Capacitor" 0603 3235,8805 r180 top value=1uF
C119 "Capacitor" 0603 3080,8575 r270 top value=0.1uF
C120 "Capacitor" 0805_HV 3000,8560 r270 top value=10uF
C121 "Capacitor" 0603 3290,8045 r90 top value=10pF
C122 "Capacitor" 1206 3305,9395 r90 bottom value=1uF
C123 "Capacitor" 1206 3060,9430 r0 bottom value=1uF
C124 "Capacitor" 0805_HV 2930,9075 r180 bottom value=10uF
C125 "Capacitor" 1206 2910,9175 r180 bottom value=1uF
C126 "Capacitor" 1206 3200,9225 r0 bottom value=1uF
C127 "Capacitor" 0603 3165,9135 r0 bottom value=0.1uF
C128 "Capacitor" 0603 3695,9460 r0 bottom value=0.1uF
C131 "Capacitor" 0603 4095,8830 r0 top value=0.22uF
C132 "Capacitor" 0603 4095,8200 r0 top value=0.22uF
C133 "Capacitor" 0603 4095,8895 r0 top value=0.1uF
C134 "Capacitor" 0603 4095,8960 r0 top value=1uF
C135 "Capacitor" 0603 4090,8265 r0 top value=0.1uF
C136 "Capacitor" 0603 4090,8330 r0 top value=1uF
C137 "Capacitor" 0603 4565,8300 r270 top value=0.01uF
C138 "Capacitor" 0603 4495,8300 r270 top value=1uF
C139 "Capacitor" 0603 4775,8300 r270 top value=0.01uF
C140 "Capacitor" 0603 4840,8300 r270 top value=0.01uF
C141 "Capacitor" 0603 4690,8750 r90 top value=1uF
C142 "Capacitor" 0603 4200,8935 r90 top value=1500pF
C143 "GRM188R72A392KA01D" 0603 3895,8760 r180 top value=3900pF
C144 "Capacitor" 0603 3695,8810 r180 top value=1500pF
C145 "Capacitor" 0603 4635,8300 r90 top value=1uF
C146 "Capacitor" 0603 4700,8300 r90 top value=0.1uF
C147 "Capacitor" 0603 4460,8640 r270 top value=2700pF
C148 "Capacitor" 0603 4460,8500 r270 top value=2700pF
C149 "Capacitor" 0603 5205,8685 r270 top value=10pF
C150 "Capacitor" 0603 4195,8295 r90 top value=1500pF
C151 "GRM188R72A392KA01D" 0603 3910,8135 r180 top value=3900pF
C152 "GRM1885C1H200JA01D" 0603 5160,8985 r90 top value=20pF
C153 "GRM1885C1H200JA01D" 0603 4735,8990 r90 top value=20pF
C154 "Capacitor" 0603 3705,8195 r180 top value=1500pF
C155 "Capacitor" 0603 4670,8160 r270 top value=1uF
C156 "Capacitor" 0603 4755,8750 r90 top value=1uF
C157 "Capacitor" 0603 5160,8215 r0 top value=1000pF
C158 "Capacitor" 1206_190 4905,8055 r270 top value=100uF
C159 "Capacitor" 1206_190 4810,8055 r270 top value=100uF
C160 "Capacitor" 0603 5325,8120 r90 top value=1uF
C161 "Capacitor" 0603 5025,7990 r0 top value=1uF
C162 "C0603C120J5GACTU" 0603 3880,8780 r90 bottom value=12pF
C163 "06033C104JAT2A" 0603 3625,8750 r270 bottom value=0.1uF
C164 "C0603C120J5GACTU" 0603 4120,8775 r270 bottom value=12pF
C165 "06033C104JAT2A" 0603 3860,7945 r0 top value=0.1uF
C166 "06033C104JAT2A" 0603 4355,8405 r180 top value=0.1uF
C167 "06033C104JAT2A" 0603 3860,8495 r90 top value=0.1uF
C168 "06033C104JAT2A" 0603 3680,8365 r180 top value=0.1uF
C169 "06033C104JAT2A" 0603 3665,8495 r90 top value=0.1uF
C170 "06035A6R8CAT2A" 0603 3445,8555 r0 bottom value=6.8pF
C171 "06035A6R8CAT2A" 0603 3470,8715 r0 bottom value=6.8pF
C172 "GRM188R6YA225KA12D" 0603 3990,8500 r270 top value=2.2uF
C173 "GRM188R71E105KA12D" 0603 4055,8500 r270 top value=1uF
C174 "06033C104JAT2A" 0603 4355,8340 r180 top value=0.1uF
C175 "GRM188R6YA225KA12D" 0603 4375,9025 r90 bottom value=2.2uF
C176 "06033C104JAT2A" 0603 4310,9025 r270 bottom value=0.1uF
C177 "06033C104JAT2A" 0603 4590,8770 r180 bottom value=0.1uF
C178 "06033C104JAT2A" 0603 4590,8705 r180 bottom value=0.1uF
C179 "GRM188R71E105KA12D" 0603 4485,9260 r0 top value=1uF
C180 "GRM188R71E105KA12D" 0603 4375,9145 r90 top value=1uF
C181 "06031C102JAT2A" 0603 4490,9050 r0 top value=1000pF
C182 "GRM188R71E105KA12D" 0603 4200,9230 r180 top value=1uF
C183 "GRM188R71E105KA12D" 0603 4295,9110 r90 top value=1uF
C184 "06031C102JAT2A" 0603 4110,9105 r90 top value=1000pF
C185 "06035A270JAT2A" 0603 4780,8895 r180 bottom value=27pF
C186 "06035A270JAT2A" 0603 4780,9095 r180 bottom value=27pF
C187 "06033C104JAT2A" 0603 4485,9230 r180 bottom value=0.1uF
C188 "Capacitor" 0603 4485,9295 r0 bottom value=1uF
C189 "GRM188R72A104KA35D" 0603L 1925,8845 r180 top value=0.1uF
C190 "C0603C101J5GACTU" 0603L 4940,6395 r0 top value=100pF
C191 "C0603C101J5GACTU" 0603L 4940,6340 r0 top value=100pF
C192 "C1608X7R1H224K080AB" 0603L 4955,6020 r270 bottom value=0.22uF
C193 "C2012X7R1C225K125AB" 0805_HV 5090,5930 r0 bottom value=2.2uF
C194 "GRM188R71E105KA12D" 0603L 4930,6265 r0 top value=1uF
C195 "C1608X7R1H224K080AB" 0603L 5245,6020 r90 bottom value=0.22uF
C196 "C0603C101J5GACTU" 0603L 5135,6575 r90 bottom value=100pF
C197 "06031C103KAT2A" 0603L 5455,6020 r0 bottom value=0.01uF
C198 "GRM188R71C474KA88D" 0603L 5380,6365 r90 top value=0.47uF
C199 "C0603C101J5GACTU" 0603L 5258.47,6348.58 r180 top value=100pF
C200 "C0603C101J5GACTU" 0603L 5255,6400 r180 top value=100pF
C201 "GRM188R71E153KA01D" 0603L 5430,6105 r90 bottom value=0.015uF
C202 "C0603C101J5GACTU" 0603L 5505,6280 r0 bottom value=100pF
C203 "C0603C101J5GACTU" 0603L 4740,5960 r180 bottom value=100pF
C204 "C1608C0G2A102J080AA" 0603L 5505,6080 r0 bottom value=1000pF
C205 "06031C103KAT2A" 0603L 5192.48,6707.52 r270 bottom value=0.01uF
C206 "HHXA800ARA390MJA0G" HXA_JA0 425,975 r270 bottom value=39uF
C207 "HHXA800ARA390MJA0G" HXA_JA0 880,975 r270 bottom value=39uF
C208 "HHXA800ARA390MJA0G" HXA_JA0 1440,3140 r90 bottom value=39uF
C209 "HHXA800ARA390MJA0G" HXA_JA0 1335,975 r270 bottom value=39uF
C210 "HHXA800ARA390MJA0G" HXA_JA0 1790,975 r270 bottom value=39uF
C211 "EMVH101GDA101MLH0S" CAPSMT_62_LH0 800,3225 r90 bottom value=100uF
C212 "HHXA800ARA390MJA0G" HXA_JA0 6760,3140 r90 bottom value=39uF
C213 "HHXA800ARA390MJA0G" HXA_JA0 6405,980 r270 bottom value=39uF
C214 "HHXA800ARA390MJA0G" HXA_JA0 6865,980 r270 bottom value=39uF
C215 "HHXA800ARA390MJA0G" HXA_JA0 7325,980 r270 bottom value=39uF
C216 "HHXA800ARA390MJA0G" HXA_JA0 7785,980 r270 bottom value=39uF
C217 "EMVH101GDA101MLH0S" CAPSMT_62_LH0 7390,3228 r90 bottom value=100uF
C218 "Capacitor" 0603 2930,7550 r0 top value=0.015uF
C221 "GRM188R61A224KA01D" 0603 2345,7085 r180 top value=0.22uF
C222 "GRM188R61A475MAAJ" 0603 2345,7020 r180 top value=4.7uF
C223 "GRM188R61A106ME69D" 0603 2505,7205 r270 top value=10uF
C224 "GRM188R60J226MEA0D" 0603 2165,7215 r90 top value=22uF
C225 "GRM188R61C104KA01D" 0603 2100,7215 r90 top value=0.1uF
C226 "GRM188R60J226MEA0D" 0603 2295,7315 r180 top value=22uF
C227 "GRM188R71E474KA12D" 0603 2295,7380 r180 top value=0.47uF
C228 "GRM188R61A106ME69D" 0603 2180,7410 r270 top value=10uF
C229 "GRM188R61A106ME69D" 0603 2110,7410 r270 top value=10uF
CC "Pogo Pad" PogoPad 3400,8045 r90 top
CS1 "TESTPOINT" TP_25MIL-SMT 2855,6635 r90 top
CS2 "TESTPOINT" TP_25MIL-SMT 2855,6940 r90 top
CV "Pogo Pad" PogoPad 2415,8440 r0 top
D1 "PMEG6010CEH,115" SOD-123F 2950,5815 r0 bottom value=60V
D2 "PMEG6010CEH,115" SOD-123F 3160,5815 r180 bottom value=60V
D3 "DIODE" SOD-523 3150,8205 r180 top value=75V
D4 "PMEG6010CEH,115" SOD-123F 4950,5815 r0 bottom value=60V
D5 "DIODE_SCHOTTKY" SOD-323 3160,8125 r180 top value=30V
D6 "B530C-13-F" SMC 5850,7875 r90 top value=30V
D7 "CDBC5100-G" SMC 6630,8205 r270 top value=100V
D10 "PMEG6010CEH,115" SOD-123F 5180,5815 r180 bottom value=60V
D11 "150060VS75000" WL-SMCW_GREEN 1645,8440 r270 top value=Green
D12 "150060YS75000" WL-SMCW_YELLOW 1915,9390 r180 top value=Yellow
DVDD_3V3 "Pogo Pad" PogoPad 4620,9115 r90 top
FID1 "Fiducial" Fiducial10-20 750,9250 r0 top
FID2 "Fiducial" Fiducial10-20 750,250 r0 top
FID3 "Fiducial" Fiducial10-20 7600,220 r0 top
FID4 "Fiducial" Fiducial10-20 750,9250 r180 bottom
FID5 "Fiducial" Fiducial10-20 750,250 r180 bottom
FID6 "Fiducial" Fiducial10-20 7600,220 r180 bottom
H1 "NY PMS 440 0025 PH" "NY PMS 440 0025 PH" 250,9220 r0 top locked
H2 "NY PMS 440 0025 PH" "NY PMS 440 0025 PH" 8050,9170 r0 top locked
H3 "NY PMS 440 0025 PH" "NY PMS 440 0025 PH" 250,250 r0 top locked
H4 "NY PMS 440 0025 PH" "NY PMS 440 0025 PH" 8050,405 r0 top
H5 "2205" KEYSTONE_2205 250,9220 r180 bottom locked
H6 "2205" KEYSTONE_2205 8050,9170 r180 bottom locked
H7 "2205" KEYSTONE_2205 250,250 r180 bottom locked
H8 "2205" KEYSTONE_2205 8050,250 r180 bottom locked
H9 "NY PMS 440 0025 PH" "NY PMS 440 0025 PH" 250,4760 r0 top
H10 "NY PMS 440 0025 PH" "NY PMS 440 0025 PH" 8050,4760 r0 top
H11 "2205" KEYSTONE_2205 250,4760 r180 bottom
H12 "2205" KEYSTONE_2205 7800,4760 r180 bottom
IBAT "Pogo Pad" PogoPad 2775,8800 r90 top
J1 "HTSW-103-07-G-S" Samtec_HTSW-103-07-G-S 3940,6340 r180 top
J2 "PEC10DAAN" SULLINS_PEC10DAAN 4250,7790 r90 top
J3 "HTSW-102-07-G-S" Samtec_HTSW-102-07-G-S 3040,6890 r0 top
J4 "HTSW-102-07-G-S" Samtec_HTSW-102-07-G-S 5700,7570 r180 top
J5 "HTSW-103-07-G-S" Samtec_HTSW-103-07-G-S 3295,7100 r180 top
J6 "Header_3x1" Samtec_HTSW-103-07-G-S 5005,7725 r90 top
J7 "Header_3x1" Samtec_HTSW-103-07-G-S 5125,7725 r90 top
J8 "Header_3x1" Samtec_HTSW-103-07-G-S 5245,7725 r90 top
J9 "108-0740-001" Johnson_108-0740-001 2350,485 r90 top
J10 "108-0740-001" Johnson_108-0740-001 5125,485 r270 top
J11 "108-0740-001" Johnson_108-0740-001 3100,485 r90 top
J12 "108-0740-001" Johnson_108-0740-001 5875,485 r270 top
J13 "HTSW-103-07-G-S" Samtec_HTSW-103-07-G-S 5940,6340 r180 top
J14 "HTSW-102-07-G-S" Samtec_HTSW-102-07-G-S 2975,8360 r270 top
J16 "HTSW-102-07-G-S" Samtec_HTSW-102-07-G-S 5465,9170 r270 top
J17 "Header_5x2" Assman_AWHW-10G-0x02-T 3665,9325 r270 top
J18 "802-10-008-10-001000" Mill-Max_802-10-008-10-001000 2600,9370 r0 top
J19 "PRPC008DAAN-RC" Sullins_xxxC008DAAN 4995,9375 r90 top
J20 "10118193-0001LF" FCI_10118193-0001LF 4330,9510 r180 top
J22 "TSW-107-07-G-S" TSW-107-07-G-S 5960,9420 r0 top
J23 "HTSW-103-07-G-S" Samtec_HTSW-103-07-G-S 6520,9420 r180 top
J25 "Header_3x1" Samtec_HTSW-103-07-G-S 6115,6995 r90 top
J26 "Header_3x1" Samtec_HTSW-103-07-G-S 6235,6995 r90 top
J27 "HTSW-102-07-G-S" Samtec_HTSW-102-07-G-S 5040,6890 r0 top
J28 "PEC10DAAN" SULLINS_PEC10DAAN 5240,7160 r90 top
J29 "HTSW-103-07-G-S" Samtec_HTSW-103-07-G-S 4285,6735 r180 top
J30 "HTSW-103-07-G-S" Samtec_HTSW-103-07-G-S 1500,8720 r270 top
J35 "HTSW-102-07-G-S" Samtec_HTSW-102-07-G-S 1925,7745 r270 top
J37 "HTSW-102-07-G-S" Samtec_HTSW-102-07-G-S 1765,7745 r270 top
L1 "74436410470" WE-HCF_2818 2640,5380 r90 top value=4.7uH
L2 "74436410470" WE-HCF_2818 5550,5370 r90 top value=4.7uH
L3 "MSS1278-473MLB" mss1278 6220,8330 r180 top value=47uH
L4 "Ferrite_Bead" 0603 3345,9210 r90 bottom value="600 ohm"
L5 "74436410470" WE-HCF_2818 2640,2965 r90 bottom value=4.7uH
L6 "74436410470" WE-HCF_2818 5550,2955 r90 bottom value=4.7uH
L7 "MPZ2012S601A" 0805_HV 2590,7220 r270 top value="600 ohm"
L8 "MPZ2012S601A" 0805_HV 2220,7525 r0 top value="600 ohm"
LBL1 "" Label_1250x250 1120,6675 r0 top
Logo2 "Pb-Free Symbol" Pb-Free_Overlay_Medium 1550,7625 r90 top
Logo3 "FCC disclaimer" FCC_disclaimer_stacked 1335,7940 r90 top
LOGO4 "CAUTION HOT SURFACE" IEC_HotSurface_Small 5995,4825 r0 top
LOGO5 "CAUTION HOT SURFACE" IEC_HotSurface_Small 2215,4740 r0 top
LOGO6 "DANGER HIGH VOLTAGE" IEC_HighVoltage_Small 2755,3690 r0 top
LOGO7 "CAUTION HOT SURFACE" IEC_HotSurface_Small 2135,2395 r0 top
LOGO8 "CAUTION HOT SURFACE" IEC_HotSurface_Small 6030,2380 r0 top
NT1 "Net-Tie" Net-Tie_10mil 3110,6130 r270 bottom net-tie
NT2 "Net-Tie" Net-Tie_10mil 6282.2,8941.37 r270 top net-tie
NT3 "Net-Tie" Net-Tie_10mil 5110,6130 r270 bottom net-tie
Q1 "TK65G10N1,RQ" DDPAK 1675,4450 r180 top
Q2 "TK65G10N1,RQ" DDPAK 2310,4280 r90 top
Q3 "TK65G10N1,RQ" DDPAK 2805,4280 r90 top
Q4 "TK65G10N1,RQ" DDPAK 1675,4950 r180 top
Q5 "TK65G10N1,RQ" DDPAK 1675,2035 r180 bottom
Q6 "TK65G10N1,RQ" DDPAK 2300,1865 r90 bottom
Q8 "TK65G10N1,RQ" DDPAK 2805,1865 r90 bottom
Q9 "TK65G10N1,RQ" DDPAK 1675,2535 r180 bottom
Q10 "TK65G10N1,RQ" DDPAK 6520,4450 r0 top
Q11 "TK65G10N1,RQ" DDPAK 5915,4280 r90 top
Q12 "TK65G10N1,RQ" DDPAK 5415,4280 r90 top
Q13 "TK65G10N1,RQ" DDPAK 6520,4950 r0 top
Q14 "SI7454DDP-T1-GE3" PowerPAK_SO-8 6920,8165 r270 top value=100V
Q15 "SI7454DDP-T1-GE3" PowerPAK_SO-8 6140,7945 r180 top value=100V
Q16 "2N7002E-T1-E3" SOT-23 1850,8475 r90 bottom value=60V
Q17 "2N7002E-T1-E3" SOT-23 1755,8470 r180 top value=60V
Q18 "2N7002E-T1-E3" SOT-23 1915,9280 r90 top value=60V
Q19 "TK65G10N1,RQ" DDPAK 6520,2035 r0 bottom
Q20 "TK65G10N1,RQ" DDPAK 5915,1865 r90 bottom
Q21 "TK65G10N1,RQ" DDPAK 5415,1865 r90 bottom
Q22 "TK65G10N1,RQ" DDPAK 6520,2535 r0 bottom
R1 "CRCW060395K3FKEA" 0603L 2745,6170 r0 bottom value=95.3k
R2 "CRCW0603634RFKEA" 0603L 2695,6070 r180 bottom value=634
R3 "CRCW06039K09FKEA" 0603L 2650,6705 r270 bottom value=9.09k
R4 "CRCW0603100KFKEA" 0603 3910,6185 r0 top value=100k
R5 "CRCW060395K3FKEA" 0603L 3410,6335 r0 bottom value=95.3k
R6 "ERJ-3EKF4992V" 0603 3520,6180 r180 bottom value=49.9k
R7 "CRCW060310K0FKEA" 0603L 2985,6695 r270 bottom value=10.0k
R8 "CRCW060395K3FKEA" 0603L 4745,6170 r0 bottom value=95.3k
R9 "CRCW06039K09FKEA" 0603L 4650,6705 r270 bottom value=9.09k
R10 "ERJ-3EKF1001V" 0603 5905,9080 r180 top value=1.00k
R11 "CRCW060310K0FKEA" 0603L 3255,6568.33 r270 bottom value=10.0k
R12 "CRCW060349K9FKEA" 0603L 3195,6950 r270 top value=49.9k
R13 "CRCW060340K2FKEA" 0603L 3205,6570 r270 bottom value=40.2k
R14 "CRCW080524R9FKEA" 0805L 2700,6260 r180 top value=24.9
R15 "ERJ-3EKF4022V" 0603 2745,6240 r0 bottom value=40.2k
R16 "WSLP27261L000FEA" RES_WSL2726 4170,2095 r270 top value=0.001
R17 "CRCW060351K1FKEA" 0603L 3505,6230 r180 bottom value=51.1k
R18 "CRCW060354K9FKEA" 0603L 2740,6015 r0 bottom value=54.9k
R19 "CRCW0603634RFKEA" 0603L 3505,6130 r180 bottom value=634
R20 "CRCW06039K09FKEA" 0603L 3240,6707.52 r90 bottom value=9.09k
R21 "WSL27261L000FEB" RES_WSL2726 3430,4950 r0 top value=0.001
R22 "CRCW080549K9FKEA" 0805_HV 2035,4390 r270 top value=49.9k
R23 "CRCW0603634RFKEA" 0603L 4695,6070 r180 bottom value=634
R24 "CRCW080549K9FKEA" 0805_HV 2240,3875 r0 top value=49.9k
R25 "CRCW080549K9FKEA" 0805_HV 2745,3875 r0 top value=49.9k
R26 "CRCW08051R00FKEA" 0805_HV 2000,4250 r0 top value=1.00
R27 "CRCW08051R00FKEA" 0805_HV 2090,3910 r270 top value=1.00
R28 "CRCW08051R00FKEA" 0805_HV 2595,3910 r270 top value=1.00
R29 "CRCW080549K9FKEA" 0805_HV 2055,4895 r270 top value=49.9k
R30 "CRCW08051R00FKEA" 0805_HV 2020,4755 r0 top value=1.00
R31 "CRCW06031R00JNEA" 0603L 2570,6680 r0 top value=1.0
R32 "WSL27261L000FEB" RES_WSL2726 4760,4960 r0 top value=0.001
R33 "CRCW080549K9FKEA" 0805_HV 6185,4670 r270 top value=49.9k
R34 "CRCW0603100KFKEA" 0603 5910,6185 r0 top value=100k
R35 "CRCW080549K9FKEA" 0805_HV 5855,3875 r0 top value=49.9k
R36 "CRCW080549K9FKEA" 0805_HV 5360,3875 r0 top value=49.9k
R37 "CRCW08051R00FKEA" 0805_HV 6315,4705 r180 top value=1.00
R38 "CRCW08051R00FKEA" 0805_HV 5705,3910 r270 top value=1.00
R39 "CRCW08051R00FKEA" 0805_HV 5210,3910 r270 top value=1.00
R40 "CRCW080549K9FKEA" 0805_HV 6185,5160 r270 top value=49.9k
R41 "CRCW08051R00FKEA" 0805_HV 6315,5200 r180 top value=1.00
R42 "CRCW06031R00JNEA" 0603L 2570,6905 r0 top value=1.0
R43 "CRCW060395K3FKEA" 0603L 5410,6335 r0 bottom value=95.3k
R44 "Resistor" 0603 4539.93,6175 r90 bottom value=0
R45 "RC0603FR-074K7L" 0603 5390,6180 r0 bottom value=4.70k
R46 "CRCW060318K2FKEA" 0603L 6378.11,9172.2 r270 top value=18.2k
R47 "PRL1632-R068-F-T1" 0612 6635,7945 r90 top value=0.068
R48 "RC0603FR-0724KL" 0603L 6052.52,9172.2 r270 top value=24.0k
R49 "RC0603FR-077K32L" 0603 6180,9185 r270 top value=7.32k
R50 "RC0603FR-0752K3L" 0603 6035,9025 r180 top value=52.3k
R51 "CRCW060310R0FKEA" 0603L 6025,8965 r0 top value=10.0
R52 "RC0603FR-0710R5L" 0603 1955,8240 r180 top value=10.5
R53 "CRCW060320K0FKEA" 0603L 6430,9235 r270 top value=20.0k
R54 "CRCW08052R00JNEA" 0805_HV 2925,5920 r180 bottom value=2.0
R55 "CRCW08052R00JNEA" 0805_HV 3255,5920 r180 bottom value=2.0
R56 "CRCW06031R00JNEA" 0603L 2735,6430 r180 top value=1.0
R57 "CRCW06031R00JNEA" 0603L 2735,6375 r180 top value=1.0
R58 "CRCW06031R00JNEA" 0603L 3470,6390 r0 top value=1.0
R59 "CRCW06031R00JNEA" 0603L 3470,6340 r0 top value=1.0
R60 "RC0603FR-074K7L" 0603 3390,6180 r0 bottom value=4.70k
R61 "Resistor" 0603L 2740,6635 r0 top value=10.0k
R62 "Resistor" 0603L 3685,7595 r0 top value=10.0k
R63 "Resistor" 0603L 2570,6730 r0 top value=10.0k
R64 "Resistor" 0603L 3580,7595 r0 top value=10.0k
R65 "Resistor" 0603 3425,7630 r0 top value=499
R67 "Resistor" 0603 3095,7465 r0 top value=0
R68 "Resistor" 0603 2620,7670 r270 top value=499
R69 "Resistor" 0603 2695,7670 r270 top value=499
R70 "1.15k" 0603 2465,7910 r180 top
R71 "Resistor" 0603 2680,8185 r270 top value=499
R72 "Resistor" 0603 2740,8625 r0 top value=0
R73 "RC0603FR-0710R5L" 0603 2805,8710 r180 top value=10.5
R74 "Resistor" 0603 3015,8705 r0 top value=10.0k
R76 "CRCW06034K42FKEA" 0603L 2000,8465 r90 top value=4.42k
R78 "CRCW060326K7FKEA" 0603L 1920,8490 r0 top value=26.7k
R80 "CRCW06031K00FKEA" 0603 2060,8475 r90 top value=1.00k
R81 "CRCW060310K0FKEA" 0603L 2395,8850 r180 top value=10.0k
R82 "Resistor" 0603 3400,8575 r270 top value=1.00k
R84 "MCT06030C1004FP500" 0603 1770,8665 r180 top value=1.00Meg
R86 "CRCW060310K0FKEA" 0603L 2395,8900 r180 top value=10.0k
R87 "ERJ-3EKF4992V" 0603 5505,6180 r180 bottom value=49.9k
R89 "CRCW060310K0FKEA" 0603L 4985,6695 r270 bottom value=10.0k
R90 "CRCW06034K99FKEA" 0603L 1645,8330 r90 top value=4.99k
R91 "CRCW06034K99FKEA" 0603L 1785,9390 r0 top value=4.99k
R92 "ERJ-3EKF1002V" 0603 4735.07,6335 r270 bottom value=10.0k
R93 "Resistor" 0603 3235,8740 r180 top value=10.0k
R94 "ERJ-3EKF1002V" 0603 4799.93,6335 r90 bottom value=10.0k
R95 "CRCW08052R00JNEA" 0805_HV 4925,5920 r180 bottom value=2.0
R96 "Resistor" 0603 2975,9300 r270 bottom value=0.51
R99 "Resistor" 0603 3565,9460 r180 bottom value=10k
R101 "CRCW060320K0FKEA" 0603L 1920,8440 r0 top value=20.0k
R102 "CRCW060310K0FKEA" 0603L 3080,6620 r0 top value=10.0k
R111 "RC0603FR-071K5L" 0603 4235,8830 r0 top value=1.50k
R112 "RC0603FR-071K5L" 0603 4030,8760 r180 top value=1.50k
R113 "Resistor" 0603 4265,8935 r270 top value=49.9
R114 "RC0603FR-071K5L" 0603 3795,8725 r90 top value=1.50k
R115 "Resistor" 0603 3595,8775 r270 top value=49.9
R116 "Resistor" 0603 3690,8880 r180 top value=100k
R117 "RC0603FR-071K5L" 0603 3695,8745 r180 top value=1.50k
R118 "Resistor" 0603 4355,8675 r0 top value=100
R119 "Resistor" 0603 4355,8610 r0 top value=100
R120 "Resistor" 0603 4625,8750 r90 top value=499
R121 "Resistor" 0603 5135,8685 r90 top value=100k
R122 "Resistor" 0603 4550,9405 r90 top value=100k
R123 "Resistor" 0603 5180,9220 r0 bottom value=100k
R124 "RC0603FR-071K5L" 0603 4230,8200 r0 top value=1.50k
R125 "Resistor" 0603 4355,8535 r0 top value=100
R126 "RC0603FR-073K3L" 0603 4040,8135 r180 top value=3.30k
R127 "Resistor" 0603 4355,8465 r0 top value=100
R128 "Resistor" 0603 4260,8295 r270 top value=49.9
R129 "RC0603FR-073K3L" 0603 3810,8100 r90 top value=3.30k
R130 "Resistor" 0603 3600,8165 r270 top value=49.9
R131 "Resistor" 0603 3705,8260 r180 top value=100k
R132 "RC0603FR-071K5L" 0603 3705,8135 r180 top value=1.50k
R133 "Resistor" 0603 4735,8160 r90 top value=0
R134 "Resistor" 0603 4990,8090 r90 top value=1.00
R135 "Resistor" 0603 4960,8845 r0 top value=0
R136 "Resistor" 0603 4765,8845 r0 top value=0
R137 "Resistor" 0603 4855,8735 r0 top value=1.00Meg
R138 "Resistor" 0603 4980,9220 r180 bottom value=1.00k
R139 "CRCW060310K0FKEA" 0603 3730,8495 r270 top value=10.0k
R140 "CRCW06031M00FKEA" 0603 3585,8535 r270 top value=1.00Meg
R141 "CRCW0603100RFKEA" 0603 3795,8495 r90 top value=100
R142 "CRCW06030000Z0EA" 0603 4015,7945 r180 top value=0
R143 "CRCW06034K87FKEA" 0603 3445,8490 r180 bottom value=4.87k
R144 "CRCW060310K0FKEA" 0603L 5080,6620 r0 top value=10.0k
R145 "CRCW06032K00FKEA" 0603 4150,8905 r0 bottom value=2.00k
R146 "CRCW060351R0JNEA" 0603 3690,8750 r270 bottom value=51
R147 "Resistor" 0603 4980,9155 r0 top value=0
R148 "CRCW060310K0FKEA" 0603L 5255,6568.33 r270 bottom value=10.0k
R149 "CRCW06031K00FKEA" 0603 4440,9025 r90 bottom value=1.00k
R150 "CRCW06031M00FKEA" 0603 4750,8995 r270 bottom value=1.00Meg
R151 "CRCW060310K0FKEA" 0603 4320,8375 r90 bottom value=10.0k
R152 "CRCW060310K0FKEA" 0603 4385,8375 r90 bottom value=10.0k
R153 "CRCW06038K06FKEA" 0603 4505,9025 r270 bottom value=8.06k
R154 "CRCW060310K0FKEA" 0603 4590,8855 r180 bottom value=10.0k
R155 "ERJ-3EKF1002V" 0603 2800,6335 r90 bottom value=10.0k
R156 "ERJ-3EKF1002V" 0603 2735,6335 r270 bottom value=10.0k
R157 "CRCW060349K9FKEA" 0603L 4185,6565 r270 top value=49.9k
R158 "CRCW060340K2FKEA" 0603L 5205,6570 r270 bottom value=40.2k
R159 "CRCW080524R9FKEA" 0805L 4700,6260 r180 top value=24.9
R160 "Resistor" 0603 3700,6115 r90 bottom value=0
R161 "Resistor" 0603 2540,6175 r90 bottom value=0
R162 "RT0603DRE072KL" 0603 3155,8305 r180 top value=2.00k
R163 "Resistor" 0603 2305,8410 r270 top value=0
R164 "Resistor" 0603 5505,8870 r90 top value=0
R165 "Resistor" 0603 5505,8635 r90 top value=0
R166 "CRCW08052R00JNEA" 0805_HV 5255,5920 r180 bottom value=2.0
R167 "ERJ-3EKF4022V" 0603 4745,6240 r0 bottom value=40.2k
R168 "Resistor" 0603 5699.93,6115 r90 bottom value=0
R169 "CRCW060351K1FKEA" 0603L 5505,6230 r180 bottom value=51.1k
R170 "CRCW060354K9FKEA" 0603L 4740,6015 r0 bottom value=54.9k
R171 "CRCW06039K09FKEA" 0603L 5240,6707.52 r90 bottom value=9.09k
R172 "CRCW0603634RFKEA" 0603L 5505,6130 r180 bottom value=634
R173 "WSL27261L000FEB" RES_WSL2726 3430,2545 r0 bottom value=0.001
R174 "CRCW080549K9FKEA" 0805_HV 2010,2245 r270 bottom value=49.9k
R175 "CRCW080549K9FKEA" 0805_HV 2360,1490 r180 bottom value=49.9k
R176 "CRCW080549K9FKEA" 0805_HV 2865,1490 r180 bottom value=49.9k
R177 "CRCW06031R00JNEA" 0603L 4735,6430 r180 top value=1.0
R178 "CRCW06031R00JNEA" 0603L 4735,6375 r180 top value=1.0
R179 "CRCW08051R00FKEA" 0805_HV 1885,2280 r0 bottom value=1.00
R180 "CRCW08051R00FKEA" 0805_HV 2510,1525 r270 bottom value=1.00
R181 "CRCW08051R00FKEA" 0805_HV 3015,1525 r270 bottom value=1.00
R182 "CRCW080549K9FKEA" 0805_HV 2010,2750 r270 bottom value=49.9k
R183 "CRCW08051R00FKEA" 0805_HV 1885,2785 r0 bottom value=1.00
R184 "WSL27261L000FEB" RES_WSL2726 4760,2545 r0 bottom value=0.001
R185 "CRCW080549K9FKEA" 0805_HV 6190,1820 r90 bottom value=49.9k
R186 "CRCW06031R00JNEA" 0603L 5470,6390 r0 top value=1.0
R187 "CRCW06031R00JNEA" 0603L 5470,6340 r0 top value=1.0
R188 "CRCW080549K9FKEA" 0805_HV 5975,1490 r180 bottom value=49.9k
R189 "CRCW080549K9FKEA" 0805_HV 5475,1490 r180 bottom value=49.9k
R190 "CRCW08051R00FKEA" 0805_HV 6315,1785 r180 bottom value=1.00
R191 "CRCW08051R00FKEA" 0805_HV 6125,1525 r270 bottom value=1.00
R192 "CRCW08051R00FKEA" 0805_HV 5625,1525 r270 bottom value=1.00
R193 "CRCW080549K9FKEA" 0805_HV 6195,2325 r270 bottom value=49.9k
R194 "CRCW08051R00FKEA" 0805_HV 6325,2295 r180 bottom value=1.00
R195 "Resistor" 0603 2930,7615 r180 top value=499
R200 "RG1608P-4871-B-T5" 0603 2465,7845 r180 top value=4.87k
R201 "RT0603DRE074R7L" 0603 2295,7445 r180 top value=4.70
S1 "Switch_PushButton" SW_TL1015AF160QG#1 5315,8720 r90 top
S2 "TL1015AF160QG" SW_TL1015AF160QG#2 3475,8860 r270 top
S3 "SW DPDT" SOT23-6_N 2200,7795 r180 top
T1 "CXS70-14-C" Panduit_CXS70-14-C 2350,485 r90 top
T2 "CXS70-14-C" Panduit_CXS70-14-C 5125,485 r90 top
T3 "CXS70-14-C" Panduit_CXS70-14-C 3100,485 r90 top
T4 "CXS70-14-C" Panduit_CXS70-14-C 5875,485 r90 top
U1 "LM5170QPHPRQ1" PHP0048D_L 3100,6260 r180 bottom
U2 "LM6142AIM/NOPB" D0008A_N 2100,8775 r270 top
U3 "TPS70950DBVR" DBV0005A_N 5730,8880 r180 top
U4 "TPS70950DBVR" DBV0005A_N 5730,8640 r180 top
U5 "LM5118MH/NOPB" MXA20A_N 6295,8875 r270 top
U6 "LM5170QPHPRQ1" PHP0048D_L 5100,6260 r180 bottom
U7 "PM-CHP-LM2664M6-6" DBV0006A_M 5735,9120 r0 top
U8 "OPA827AIDR" D0008A_L 1900,8045 r90 top
U9 "SN74LV4053ATPWRQ1" PW0016A_L 3175,7615 r0 top
U10 "SN74LVC1G04QDBVRQ1" DBV0005A_N 2135,9315 r180 bottom
U11 "SN74LV1T00DBVR" DBV0005A_N 2090,8465 r180 bottom
U12 "SN74LV1T32DBVR" DBV0005A_N 1875,9290 r180 bottom
U13 "INA828ID" D0008A_N 2655,7890 r90 top
U14 "OPA827AIDR" D0008A_L 2655,8450 r90 top
U15 "TLV07IDR" D0008A_N 3235,8500 r270 top
U16 "TI-REF5050D8" D0008A_N 3060,9360 r180 top
U17 "DACx0004DMD" DMD0014A 3115,8985 r270 top
U19 "THS4561IDGKR" DGK0008A_N 3895,8875 r180 top
U20 "THS4561IDGKR" DGK0008A_N 3900,8255 r180 top
U21 "ADS131A04IPBSR" PBS0032A_L 4705,8525 r0 top
U22 "TI-REF5025DGK8" DGK0008A_N 5155,8100 r180 top
U23 "TM4C1294NCPDTI3R" PDT0128A 3885,8320 r90 bottom
U24 "TPS73733DRVR" DRV0006A 4475,9150 r90 top
U25 "TPS71718DCKR" DCK0005A_N 4200,9120 r270 top
U26 "TPD4S012DRYR" DRY0006A 4325,9255 r270 top
U27 "USB3320C-EZK" Microchip_32QFN-3304-5x5B 4380,8820 r90 bottom
U28 "24AA256-I/ST" TSSOP-8 4380,8110 r90 bottom
U29 "LM7705MM/NOPB" MUA08A_N 2345,7200 r180 top
V1.8 "Pogo Pad" PogoPad 4375,8995 r90 top
V-5 "Pogo Pad" PogoPad 5350,9120 r0 top
VBAT "Pogo Pad" PogoPad 2060,8155 r90 top locked
VREF_ADC "Pogo Pad" PogoPad 4990,8250 r90 top
VREF_DAC "Pogo Pad" PogoPad 3055,9210 r90 top
VREF_LV "Pogo Pad" PogoPad 1750,8760 r90 top
Y1 "XTAL_4P_13_G24" CTS_407 4945,9000 r270 top
Y2 "ABM3-25.000MHZ-D2Y-T" XTAL_ABM3 4000,8825 r270 bottom
Y3 "SSPT7F-7PF20-R" Seiko_SSP-T 3410,8635 r90 bottom
Y4 "ABM3-24.000MHZ-D2Y-T" XTAL_ABM3 4625,9010 r270 bottom
ZZ1 "This Assembly Note is for PCB labels only" AssemblyNoteLabel -1245,10470 r0 top
ZZ2 "These assemblies are ESD sensitive, ESD precautions shall be observed." AssemblyNote -1245,10370 r0 top
ZZ3 "These assemblies must be clean and free from flux and all contaminants. Use of no clean flux is not acceptable." AssemblyNote -1245,10270 r0 top
ZZ4 "These assemblies must comply with workmanship standards IPC-A-610 Class 2, unless otherwise specified." AssemblyNote -1245,10170 r0 top

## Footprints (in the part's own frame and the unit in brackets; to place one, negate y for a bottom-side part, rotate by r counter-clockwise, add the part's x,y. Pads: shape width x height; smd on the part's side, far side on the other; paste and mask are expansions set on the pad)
0603 [mm] "0603 from SM-752 data"
  rect 1x0.95 smd: 1(-0.8,0) 2(0.8,0)
  silkscreen extent -1.52,-0.69 1.52,0.69, body extent -0.87,-0.47 0.87,0.47, height 1
0603L [mm] "0603 from SM-752 data"
  rect 0.8x0.85 smd: 1(-0.7,0) 2(0.7,0)
  silkscreen extent -0.07,-0.33 0.07,0.33, body extent -0.87,-0.47 0.87,0.47, height 1
0612 [mm] "Panasonic recommended land pattern, fb97d03ed01.pdf dated April 2008"
  rect 0.65x2.75 smd: 1(-0.775,0) 2(0.775,0)
  silkscreen extent -1.1,-1.9 1.1,1.9, body extent -0.9,-1.7 0.9,1.7, height 0.85
0805_HV [mil] "0805 with 30mil clearance between pads"
  rect 50x63 smd: 1(-40,0) 2(40,0)
  silkscreen extent -74,-40 74,40, body extent -43,-29 43,29, height 57
0805L [mm] "0805 from SM-752 data"
  rect 1.1x1.4 smd: 1(-0.75,0) 2(0.75,0)
  body extent -1.1,-0.72 1.1,0.72, height 1.45
1206 [mm] "1206 from SM-752 data"
  rect 1.3x1.85 smd: 1(-1.45,0) 2(1.45,0)
  silkscreen extent -2.4,-1.21 2.4,1.21, body extent -1.7,-0.9 1.7,0.9, height 1.35
1206_190 [mm] "1206_190"
  rect 1.1x1.6 smd: 1(-1.7,0) 2(1.7,0)
  silkscreen extent -0.9,-1 0.9,1, body extent -1.75,-0.95 1.75,0.95, height 1.9
2220_250 [mm] "2220"
  rect 1.6x5.3 smd: 1(-2.6,0) 2(2.6,0)
  silkscreen extent -3.69,-2.94 3.69,2.94, body extent -2.95,-2.62 2.95,2.62, height 2.5
2220_280 [mm] "Chip Capacitor, Body 5.7x5.0mm, IPC Medium Density"
  rect 1.6x5.3 smd: 1(-2.6,0) 2(2.6,0)
  silkscreen extent -3.69,-2.94 3.69,2.94, body extent -2.95,-2.62 2.95,2.62, height 2.8
AssemblyNote [mil] "Assembly Note"
AssemblyNoteLabel [mil] "Assembly Note for PCB Labels"
Assman_AWHW-10G-0x02-T [mm] "Header, 2.54mm, 5x2, TH"
  rect 1.55x1.55 hole 1.02: 1(-1.27,5.08)
  round 1.55 hole 1.02: 2(1.27,5.08) 3(-1.27,2.54) 4(1.27,2.54) 5(-1.27,0) 6(1.27,0) 7(-1.27,-2.54) 8(1.27,-2.54) 9(-1.27,-5.08) 10(1.27,-5.08)
  silkscreen extent -4.9,-10.31 4.47,10.31, body extent -4.47,-10.31 4.47,10.31, height 9.15
CAPSMT_62_HC0 [mm] "8 x 12mm:  Chemi-Con HC0"
  rect 4.2x2.2 smd: 1(-3.638,0.012) 2(3.662,0.012)
  silkscreen extent -4.24,-4.24 4.26,4.26, body extent -4.24,-4.24 4.26,4.26, height 12.5
CAPSMT_62_JA0 [mm] "10 x 10mm:  Chemi-Con JA0"
  rect 4.4x2.2 smd: 1(-4.45,0) 2(4.45,0)
  silkscreen extent -5.25,-5.25 5.25,5.25, body extent -5.25,-5.25 5.25,5.25, height 10.5
CAPSMT_62_LH0 [mm] "16 x 16.5mm:  Chemi-Con LH0"
  rect 7.8x9.6 smd: 1(-6.25,0) 2(6.25,0)
  silkscreen extent -8.55,-8.55 8.55,8.55, body extent -8.55,-8.55 8.55,8.55, height 17
CR_1000x1270 [mm] "SMD, 2-Leads, Dia 10.5mm, Pin Spacing 8mm"
  rect 4x2 smd: 1(-4,0) 2(4,0)
  silkscreen extent -7.4,-5.25 5.25,5.25, body extent -5.25,-5.25 5.25,5.25, height 12.71
CTS_407 [mm] "SMD, 4-Leads, Body 7.2x5.2mm"
  rect 1.4x2.2 smd: 1(-1.27,3.2) 2(-1.27,-3.2) 3(1.27,-3.2) 4(1.27,3.2)
  silkscreen extent -2.65,-3.6 2.6,4.15, body extent -2.6,-3.6 2.6,3.6, height 1.3
D0008A_L [mm] "SOIC, 8-Leads, Body 4.9x3.9mm, Pitch 1.27mm, IPC High Density"
  oval 1.25x0.55 smd: 1(-2.625,1.905) 2(-2.625,0.635) 3(-2.625,-0.635) 4(-2.625,-1.905) 5(2.625,-1.905) 6(2.625,-0.635) 7(2.625,0.635) 8(2.625,1.905)
  silkscreen extent -3.1,-2.5 0.9,2.5, body extent -3,-2.45 3,2.45, height 1.63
